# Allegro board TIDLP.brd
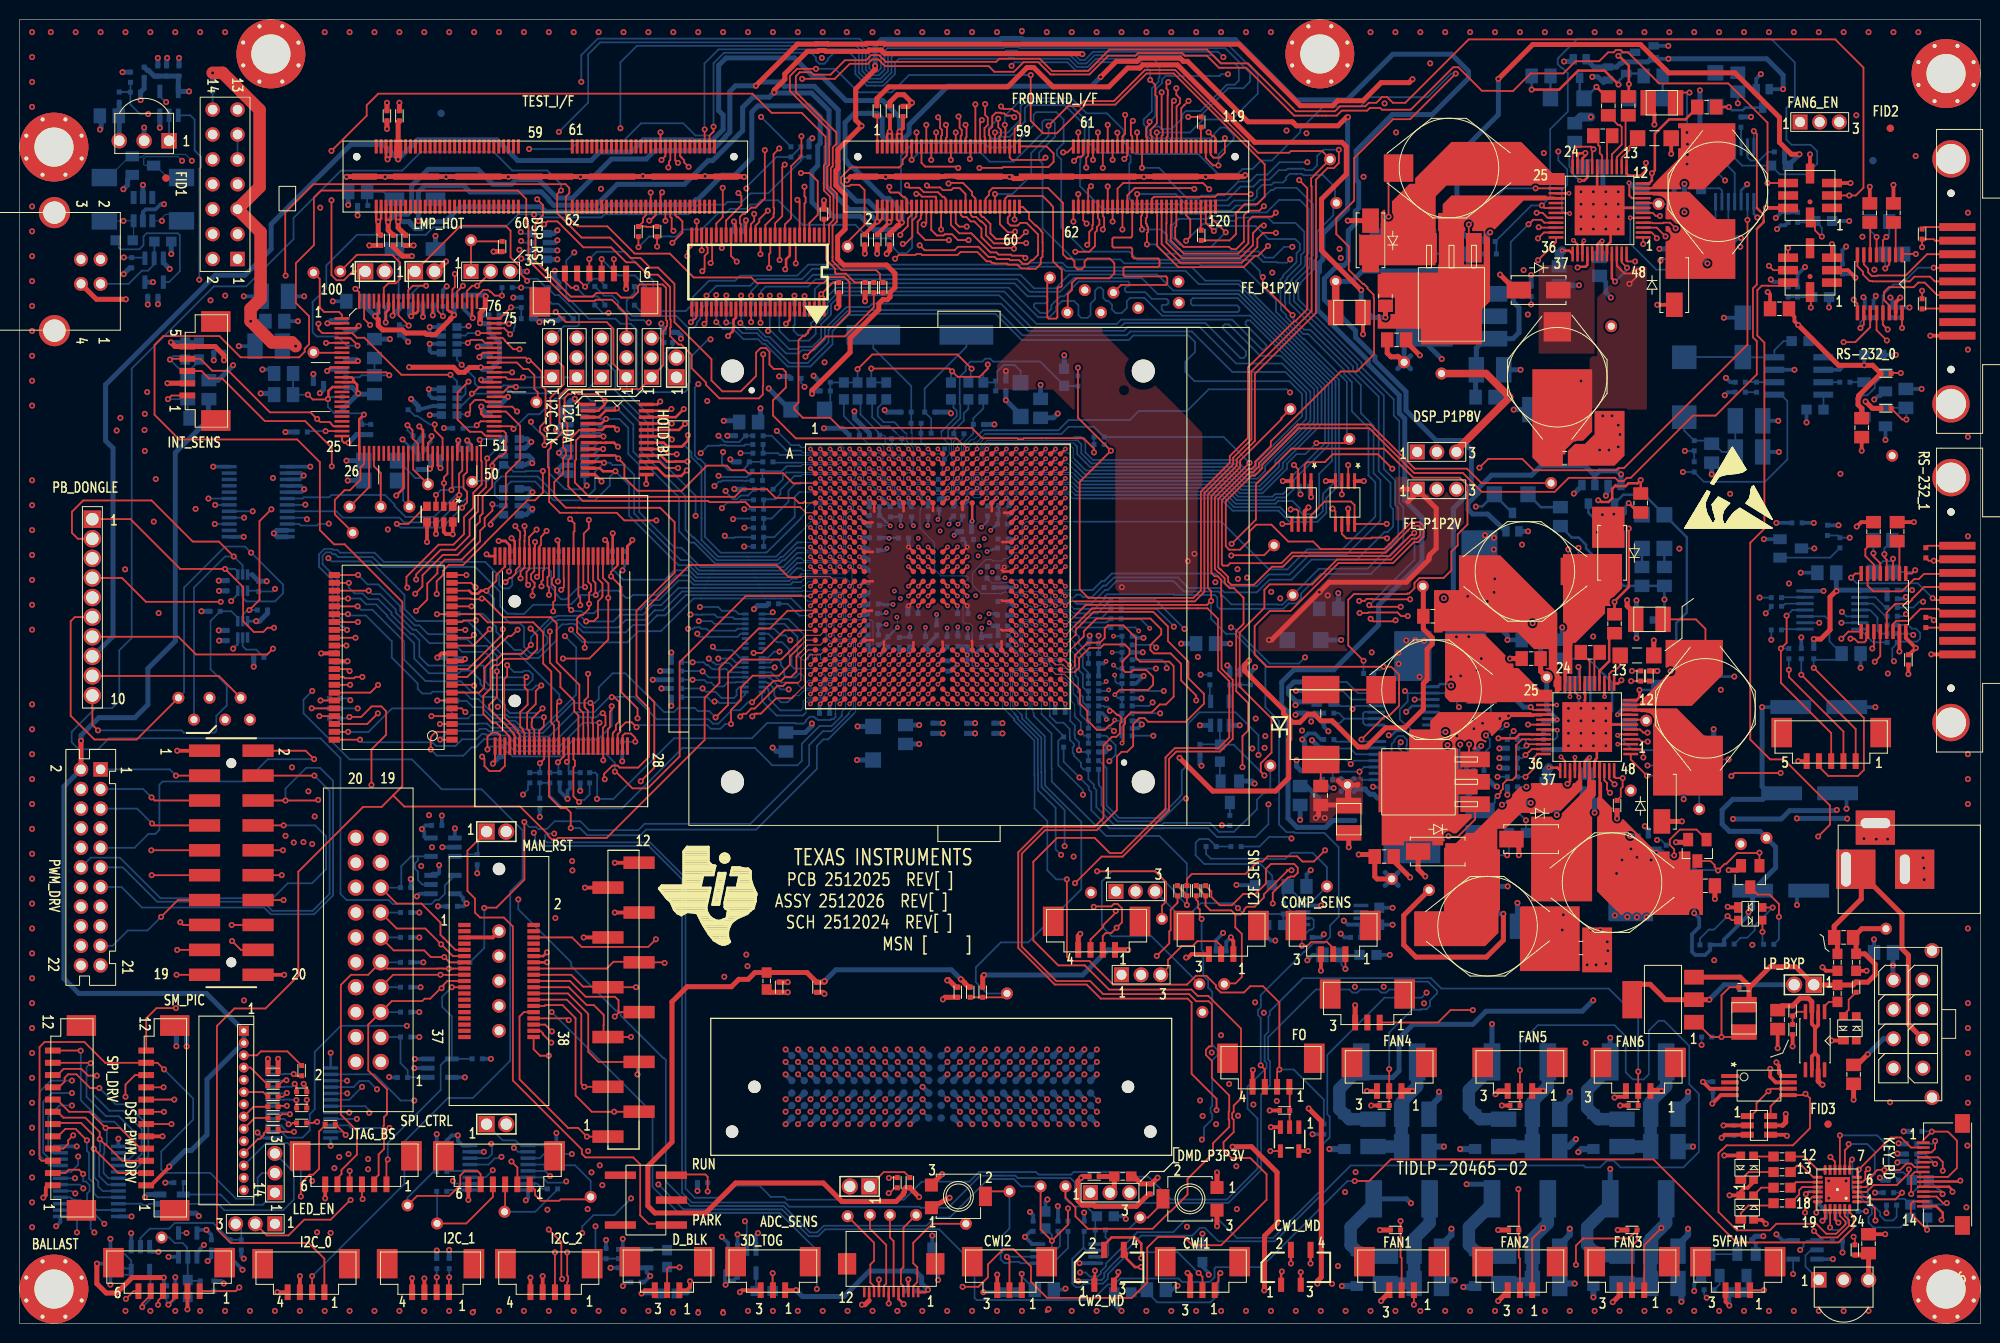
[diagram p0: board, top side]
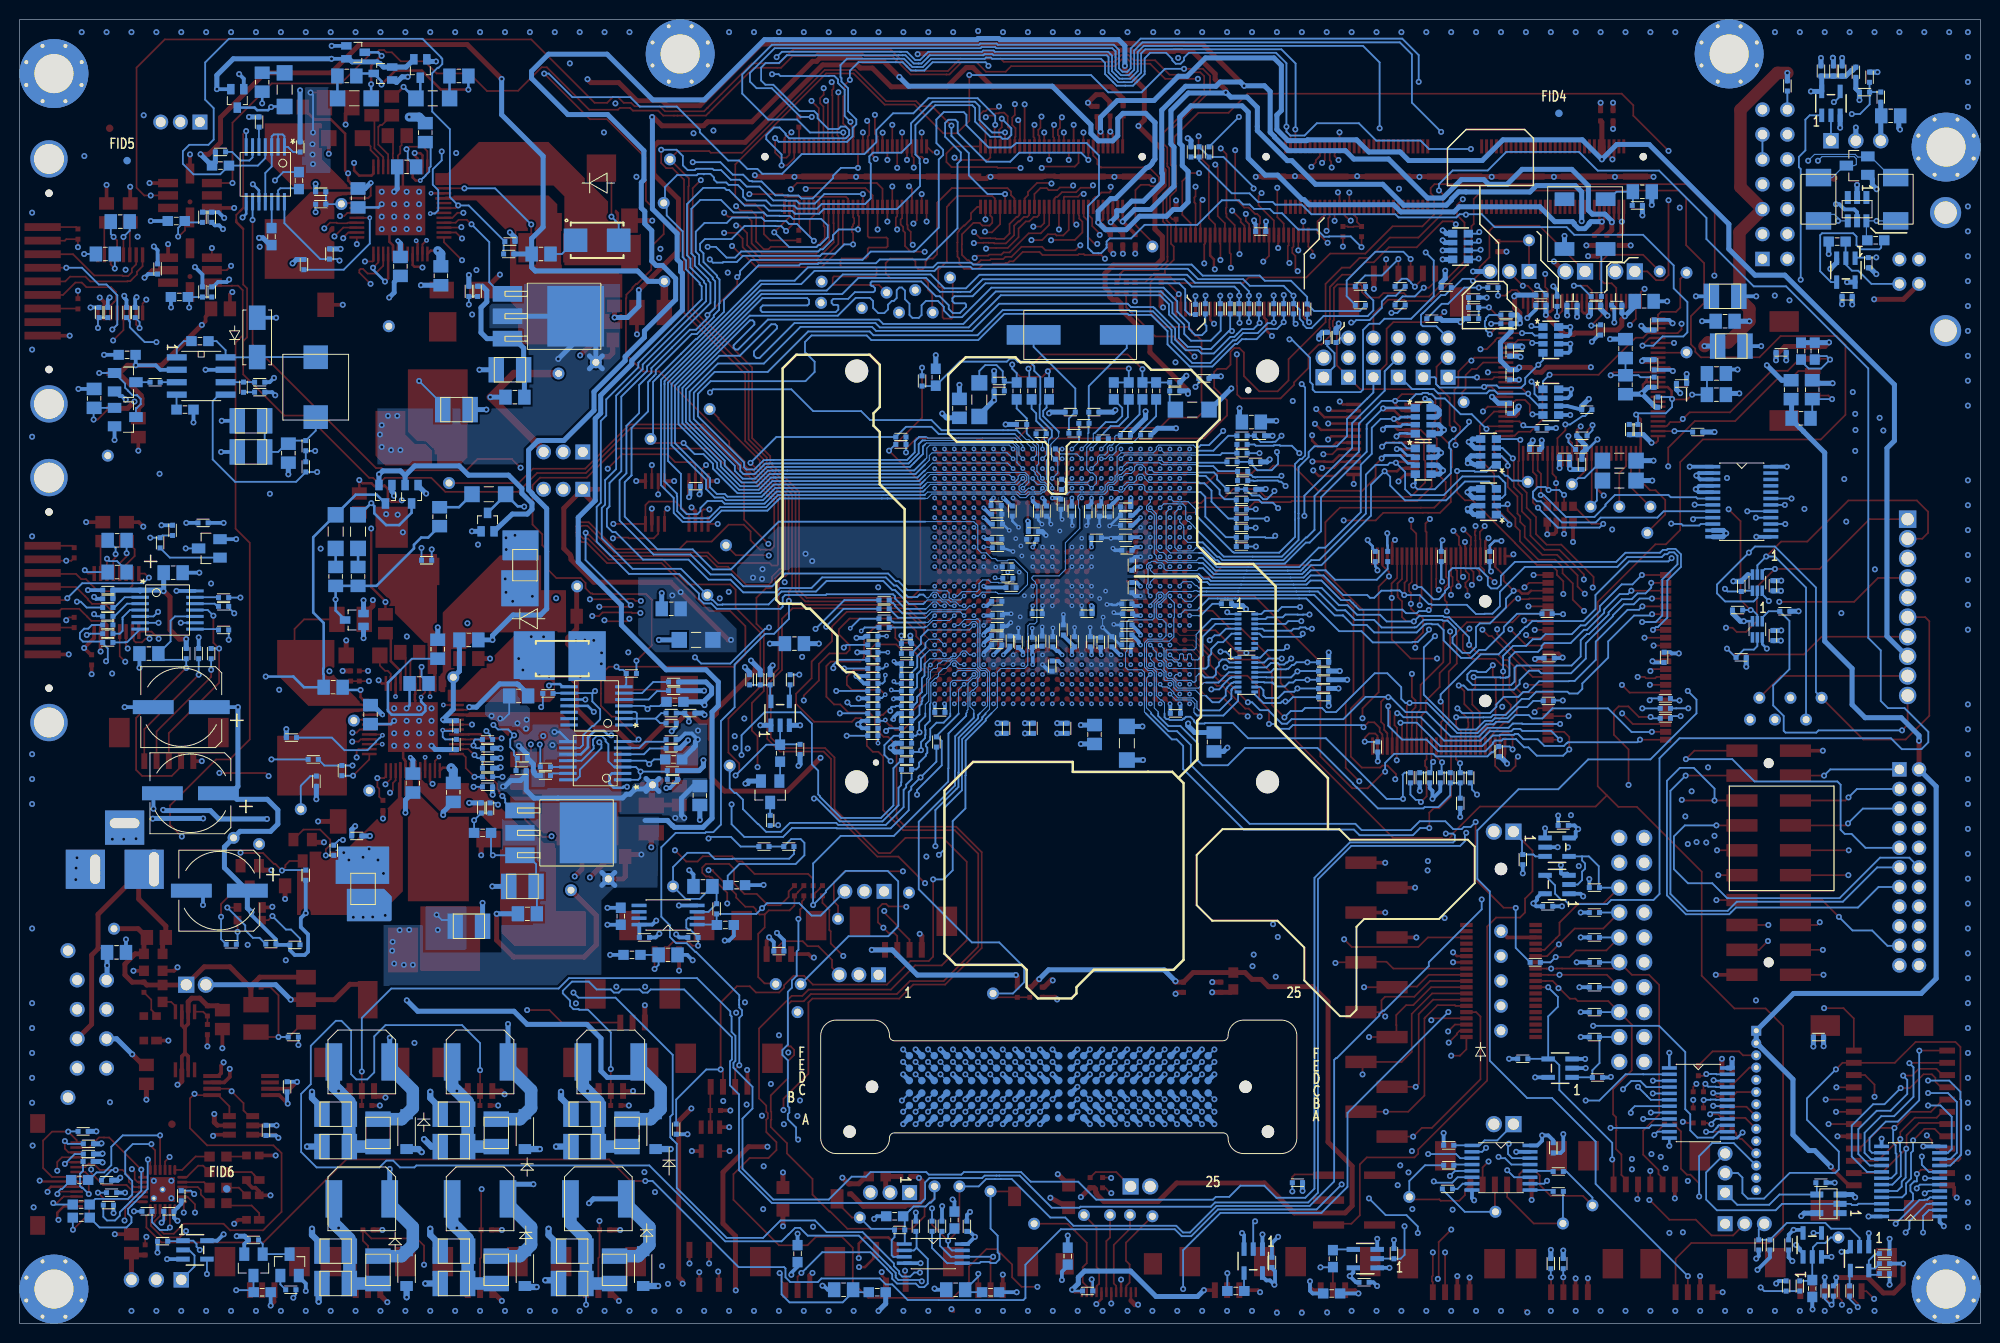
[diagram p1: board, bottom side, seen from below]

Outline 200 x 132.99 mm; copper layers: TOP, LY2GND, LY3, LY4, LY5PWR, BOTTOM. Coordinates in mm from the lower left corner of the outline.
Outline path: 0,132.99 0,0 200,0 200,132.99 0,132.99

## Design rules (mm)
net group DDA00: nets DDA00_N DDA00_P
net group 10: nets CWCTR2 CWY1A CWY1B CWY1C CWY2A CWY2B CWY2C OUT1A_SNUB OUT1B OUT1B_SNUB OUT1C OUT1C_SNUB OUT2A OUT2A_SNUB OUT2B OUT2B_SNUB OUT2C OUT2C_SNUB
net group 20: nets FAN1_SW FAN2_SW FAN4_SW FAN5_SW FAN6_SW FAN6_SW_JUMP
net group 30: nets BT656_A_CLK P_CLK1 P_CLK2 P_CLK3 XTAL_IN XTAL_OUT
net group BT656: nets BT656_CLK BT656_D0 BT656_D1 BT656_D2 BT656_D3 BT656_D4 BT656_D5 BT656_D6 BT656_D7 BT656_D8 BT656_D9
net group BT656_A: nets BT656_A_D0 BT656_A_D1 BT656_A_D2 BT656_A_D3 BT656_A_D4 BT656_A_D5 BT656_A_D6 BT656_A_D7 BT656_A_D8 BT656_A_D9
net group BT656_B: nets BT656_B_CLK BT656_B_D0 BT656_B_D1 BT656_B_D2 BT656_B_D3 BT656_B_D4 BT656_B_D5 BT656_B_D6 BT656_B_D7 BT656_B_D8 BT656_B_D9
net group CLK: nets A_SSP0_CLK ADC_SCLK NC0119 NC0120 OCLKA_RES SP_WAVE_CLK SSP0_CLK_DMD SSP1_CLK SSP2_CLK TRACECLK XCLKIN XCLKOUT
net group DDA: nets DCLKA_N DCLKA_P DDA01_N DDA01_P DDA02_N DDA02_P DDA03_N DDA03_P DDA04_N DDA04_P DDA05_N DDA05_P DDA06_N DDA06_P DDA07_N DDA07_P DDA08_N DDA08_P DDA09_N DDA09_P DDA10_N DDA10_P DDA11_N DDA11_P DDA12_N DDA12_P DDA13_N DDA13_P DDA14_N DDA14_P DDA15_N DDA15_P SCTRLA_N SCTRLA_P
net group DDB: nets DCLKB_N DCLKB_P DDB00_N DDB00_P DDB01_N DDB01_P DDB02_N DDB02_P DDB03_N DDB03_P DDB04_N DDB04_P DDB05_N DDB05_P DDB06_N DDB06_P DDB07_N DDB07_P DDB08_N DDB08_P DDB09_N DDB09_P DDB10_N DDB10_P DDB11_N DDB11_P DDB12_N DDB12_P DDB13_N DDB13_P DDB14_N DDB14_P DDB15_N DDB15_P SCTRLB_N SCTRLB_P
net group DIFF_SP: nets USB_DAT_N USB_DAT_NS USB_DAT_P USB_DAT_PS
net group GPIO: nets GPIO_40 GPIO_41 GPIO_42 GPIO_43 GPIO_44 GPIO_45 GPIO_46 GPIO_47 GPIO_48 GPIO_49 GPIO_50
net group P1_CLK BUS: nets AFE_CLK EXT_CLK P1_A0 P1_A1 P1_A2 P1_A3 P1_A4 P1_A5 P1_A6 P1_A7 P1_A8 P1_A9 P1_B0 P1_B1 P1_B2 P1_B3 P1_B4 P1_B5 P1_B6 P1_B7 P1_B8 P1_B9 P1_C0 P1_C1 P1_C2 P1_C3 P1_C4 P1_C5 P1_C6 P1_C7 P1_C8 P1_C9 P1_HSYNC P1_VSYNC P2_A0 P2_A1 P2_A2 P2_A3 P2_A4 P2_A5 P2_A6 P2_A7 P2_A8 P2_A9 P2_B0 P2_B1 P2_B2 P2_B3 P2_B4 P2_B5 P2_B6 P2_B7 P2_B8 P2_B9 P2_C0 P2_C1 P2_C2 P2_C3 P2_C4 P2_C5 P2_C6 P2_C7 P2_C8 P2_C9 P2_HSYNC P_DATAEN1 P_DATAEN2
net group PM_: nets PM_ADR_21 PM_ADR_22 PM_BLS0 PM_BLS0S PM_BLS1 PM_BLS1S PM_DAT_0 PM_DAT_1 PM_DAT_2 PM_DAT_3 PM_DAT_4 PM_DAT_5 PM_DAT_6 PM_DAT_7 PM_DAT_8 PM_DAT_9 PM_DAT_10 PM_DAT_11 PM_DAT_12 PM_DAT_13 PM_DAT_14 PM_DAT_15 PM_OESZ PM_OEZ PM_SRAM_CSSZ PM_SRAM_CSZ PM_WESZ PM_WEZ
net group PWR: nets A1P8V DMD_P3P3V DMDSPARE0 FE_P1P2V LP_P3P3V MC_VCC P2P5V_CONN P3P3V_CONN P3P3V_EX P3P3V_LP P5V P5V_CONN P5V_IR P5V_IR_CONN P12V_FIL P12V_IN SWNODE2_CORE
net group TRACEPKT_BGA: nets PIPESTAT0R PIPESTAT1R PIPESTAT2R TRACECLKR TRACEPKT0R TRACEPKT1R TRACEPKT2R TRACEPKT3R TRACEPKT4R TRACEPKT5R TRACEPKT6R TRACEPKT7R TRACESYNCR
net group TRACEPT_BUS: nets PIPESTAT0 PIPESTAT1 PIPESTAT2 TRACEPKT0 TRACEPKT1 TRACEPKT2 TRACEPKT3 TRACEPKT4 TRACEPKT5 TRACEPKT6 TRACEPKT7 TRACESYNC
net group U53: nets A1P8V_SENSE CWCTR1 FAN3_SW MTR_ARSTZ N16827292 N16830205 N16830576 N16830606 OCLKA OUT1A P_INTZ PGOOD PMD1K_CP1 PMD1K_FB_LIN1 PMD1K_FB_MOT1 PMD1K_FB_P3P3V PMD1K_FB_P5V PMD1K_GD_CORE PMD1K_GM_IN1 PMD1K_SENSE_MOT1 PMD1K_VCP PMD1K_VREG PMD_INTZ POSENSE PSENS PWRGOOD SSP0_CLK SWNODE_CORE SWNODE_MOT SWNODE_P3P3V SWNODE_P5V

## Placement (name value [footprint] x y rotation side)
ASY1  -  []  20.32 49.53 180 bottom
C1  22 uF  [CAP_1210]  167.51 124.52 0 top
C2  -  [CAP_0402]  37.47 123.19 90 top
C3  -  [CAP_0402]  38.73 123.19 90 top
C4  -  [CAP_0402]  88.77 123.7 90 top
C5  -  [CAP_0402]  90.11 123.63 90 top
C6  -  [CAP_0805]  161.48 121.16 0 top
C7  -  [CAP_0805]  188.72 113.28 90 top
C8  -  [CAP_0805]  191.13 113.28 90 top
C9  -  [CAP_0402]  36.83 110.49 270 top
C10  -  [CAP_0402]  38.1 110.49 270 top
C11  -  [CAP_0402]  39.37 110.49 270 top
C12  -  [CAP_0402]  86.21 110.54 270 top
C13  -  [CAP_0402]  87.48 110.54 270 top
C14  -  [CAP_0402]  88.75 110.54 270 top
C15  -  [CAP_1206]  80.39 93.22 180 bottom
C16  -  [CAP_1206]  102.11 94.23 270 bottom
C17  47 uF  [CAP_1210]  135.64 103.12 180 top
C18  -  [CAP_0805]  179.51 103.5 180 top
C19  -  [CAP_0805]  187.9 91.38 270 top
C20  -  [CAP_0805]  189.1 80.77 90 top
C21  -  [CAP_0805]  191.52 80.77 90 top
C22  22 uF  [CAP_1210]  166.24 71.82 0 top
C23  -  [CAP_0805]  154.18 67.82 0 top
C24  -  [CAP_0805]  160.21 68.45 0 top
C25  -  [CAP_0402]  166.24 66.04 270 top
C26  -  [CAP_0402]  192.66 67.69 90 top
C27  47 uF  [CAP_1210]  135.57 51.44 90 top
C28  -  [CAP_0603]  185.42 36.83 90 top
C29  -  [CAP_0603]  187.32 36.83 90 top
C30  -  [CAP_0402]  77.47 34.29 270 top
C31  -  [CAP_0402]  81.28 34.29 90 top
C32  10 uF  [CAP_1210]  175.9 31.11 270 top
C33  -  [CAP_0805]  179.32 30.99 90 top
C34  -  [CAP_0402]  25.84 25.65 180 top
C35  -  [CAP_0402]  109.6 14.99 0 top
C36  -  [CAP_0402]  115.32 13.72 90 top
C37  -  [CAP_0805]  188.59 8.13 270 top
C500  -  [CAP_0805]  175.26 126.62 90 bottom
C501  -  [CAP_0805]  166.62 127.25 0 bottom
C502  -  [CAP_0805]  155.19 127.25 0 bottom
C503  -  [CAP_0402]  16.26 127.76 270 bottom
C504  -  [CAP_0402]  14.1 127.76 270 bottom
C505  -  [CAP_0805]  158.62 121.48 90 bottom
C506  -  [CAP_0805]  9.14 123.19 0 bottom
C507  -  [CAP_0805]  189.74 112.39 0 bottom
C508  -  [CAP_0402]  181.36 112.84 270 bottom
C509  -  [CAP_0402]  180.4 112.84 270 bottom
C510  -  [CAP_0603]  179.51 118.11 0 bottom
C511  -  [CAP_0402]  169.29 115.44 180 bottom
C512  -  [CAP_0805]  165.48 114.81 90 bottom
C513  -  [CAP_0805]  160.53 117.98 0 bottom
C514  -  [CAP_0402]  34.99 114.05 180 bottom
C515  -  [CAP_0805]  191.26 109.09 0 bottom
C516  -  [CAP_0402]  185.93 107.57 90 bottom
C517  -  [CAP_0402]  181.36 105.22 270 bottom
C518  -  [CAP_0402]  180.4 105.22 270 bottom
C519  -  [CAP_0805]  161.16 107.82 90 bottom
C520  -  [CAP_0805]  157.04 106.87 90 bottom
C521  -  [CAP_0402]  100.08 95.12 0 bottom
C522  -  [CAP_0402]  82.17 96.01 180 bottom
C523  -  [CAP_0402]  73.41 111.38 0 bottom
C524  -  [CAP_0402]  51.69 104.65 180 bottom
C525  22 uF  [CAP_1210]  26.04 104.78 0 bottom
C526  -  [CAP_0402]  13.59 104.78 180 bottom
C527  -  [CAP_0603]  189.04 98.81 180 bottom
C528  -  [CAP_0603]  181.61 100.2 180 bottom
C529  47 uF  [CAP_1210]  149.99 97.28 180 bottom
C530  -  [CAP_0402]  48.01 99.19 90 bottom
C531  -  [CAP_0402]  44.83 103.89 0 bottom
C532  -  [CAP_0402]  41.66 103.89 180 bottom
C533  -  [CAP_0402]  39.24 103.89 0 bottom
C534  -  [CAP_0402]  37.08 103.89 0 bottom
C535  -  [CAP_0805]  34.29 104.27 180 bottom
C536  -  [CAP_0402]  33.27 101.85 90 bottom
C537  -  [CAP_0402]  33.27 97.79 270 bottom
C538  22 uF  [CAP_1210]  25.4 99.69 180 bottom
C539  -  [CAP_0603]  16.89 99.19 90 bottom
C540  -  [CAP_0805]  192.41 94.36 90 bottom
C541  -  [CAP_0603]  183.13 93.22 0 bottom
C542  -  [CAP_0402]  177.16 95.5 270 bottom
C543  47 uF  [CAP_1210]  176.4 92.08 0 bottom
C544  -  [CAP_0402]  175.51 96.01 180 bottom
C545  47 uF  [CAP_1210]  155.45 93.22 0 bottom
C546  -  [CAP_0402]  93.71 85.59 90 bottom
C547  -  [CAP_0402]  89.47 90.25 180 bottom
C548  -  [CAP_0402]  87.21 90.6 180 bottom
C549  -  [CAP_0402]  95.8 90.75 0 bottom
C550  -  [CAP_0402]  85.14 90.62 180 bottom
C551  -  [CAP_0603]  106.55 96.52 270 bottom
C552  -  [CAP_0805]  104.14 93.34 90 bottom
C553  -  [RES_0402]  90.42 92.96 180 bottom
C554  -  [RES_0402]  92.84 92.96 0 bottom
C555  -  [CAP_0805]  74.36 91.95 180 bottom
C556  -  [CAP_0402]  48.01 96.77 270 bottom
C557  -  [CAP_0402]  48.01 93.34 270 bottom
C558  -  [CAP_0805]  36.2 95.76 270 bottom
C559  -  [CAP_0402]  35.81 91.19 270 bottom
C560  -  [CAP_0402]  34.92 91.19 270 bottom
C561  -  [CAP_0402]  33.27 96.01 270 bottom
C562  -  [CAP_0402]  32.89 93.98 270 bottom
C563  -  [CAP_0805]  26.92 94.74 180 bottom
C564  -  [CAP_0805]  19.3 95.25 90 bottom
C565  -  [CAP_0805]  17.14 95.25 90 bottom
C566  47 uF  [CAP_1210]  176.4 88.9 0 bottom
C567  -  [CAP_0402]  131.06 85.41 0 bottom
C568  -  [CAP_0402]  100.39 83.44 180 bottom
C569  -  [CAP_0402]  93.79 83.57 270 bottom
C570  -  [CAP_0402]  87.19 83.31 0 bottom
C571  -  [CAP_0402]  45.47 89.15 0 bottom
C572  -  [CAP_0402]  42.42 88.39 180 bottom
C573  -  [CAP_0402]  40.77 89.15 180 bottom
C574  -  [CAP_1206]  36.83 88.01 180 bottom
C575  -  [CAP_1206]  36.83 85.98 180 bottom
C576  -  [CAP_0805]  190.06 79.88 0 bottom
C577  -  [CAP_0805]  190.06 76.64 0 bottom
C578  -  [CAP_0805]  184.34 76.58 180 bottom
C579  -  [CAP_0402]  181.29 81.66 180 bottom
C580  -  [CAP_0805]  167.77 76.2 90 bottom
C581  -  [CAP_0805]  165.48 76.2 90 bottom
C582  -  [CAP_0805]  157.16 82.29 90 bottom
C583  22 uF  [CAP_1210]  148.46 77.34 270 bottom
C584  -  [CAP_0402]  97.8 91.7 0 bottom
C585  -  [CAP_0402]  99.25 77.19 180 bottom
C586  -  [CAP_0402]  100.33 82.55 180 bottom
C587  -  [CAP_0402]  100.33 80.01 180 bottom
C588  -  [CAP_0402]  100.27 79.12 180 bottom
C589  -  [CAP_0402]  98.87 75.06 180 bottom
C590  -  [CAP_0402]  100.27 81.53 180 bottom
C591  -  [CAP_0402]  98.74 82.87 270 bottom
C592  -  [CAP_0402]  96.76 79.98 0 bottom
C593  -  [CAP_0402]  96.58 80.77 180 bottom
C594  -  [CAP_0402]  96.2 82.87 270 bottom
C595  -  [CAP_0402]  95.25 82.87 270 bottom
C596  -  [CAP_0402]  92.67 82.85 270 bottom
C597  -  [CAP_0402]  91 82.8 270 bottom
C598  -  [CAP_0402]  90.17 80.14 180 bottom
C599  -  [CAP_0402]  89.85 82.87 270 bottom
C600  -  [CAP_0402]  88.84 82.8 270 bottom
C601  -  [CAP_0402]  87.19 82.42 0 bottom
C602  -  [CAP_0402]  87.19 81.41 0 bottom
C603  -  [CAP_0402]  87.19 80.14 0 bottom
C604  -  [CAP_0402]  87.06 78.87 0 bottom
C605  -  [CAP_0402]  86.55 77.34 90 bottom
C606  -  [CAP_0402]  54.99 78.23 90 bottom
C607  -  [CAP_0402]  191.01 74.8 180 bottom
C608  -  [CAP_0805]  133.54 72.9 0 bottom
C609  -  [CAP_1206]  131 69.72 0 bottom
C610  -  [CAP_0805]  120.97 69.34 0 bottom
C611  -  [CAP_0402]  112.97 70.1 0 bottom
C612  -  [CAP_0402]  100.33 73.66 180 bottom
C613  -  [CAP_0402]  100.33 70.17 180 bottom
C614  -  [CAP_0402]  100.33 69.22 0 bottom
C615  -  [CAP_0402]  100.27 72.26 180 bottom
C616  -  [CAP_0402]  100.27 71.12 180 bottom
C617  -  [CAP_0402]  99 69.6 90 bottom
C618  -  [CAP_0402]  98.11 69.47 90 bottom
C619  -  [CAP_0402]  96.71 69.47 90 bottom
C620  -  [CAP_0402]  96.2 72.39 180 bottom
C621  -  [CAP_0402]  95.69 69.6 90 bottom
C622  -  [CAP_0402]  94.61 69.53 90 bottom
C623  -  [CAP_0402]  93.54 70.74 90 bottom
C624  -  [CAP_0402]  92.39 69.53 90 bottom
C625  -  [CAP_0402]  91.12 72.39 0 bottom
C626  -  [CAP_0402]  90.81 69.53 90 bottom
C627  -  [CAP_0402]  89.73 69.47 90 bottom
C628  -  [CAP_0402]  88.58 69.53 90 bottom
C629  -  [CAP_0402]  87.06 73.41 0 bottom
C630  -  [CAP_0402]  87.06 71.25 0 bottom
C631  -  [CAP_0402]  87.06 70.23 0 bottom
C632  -  [CAP_0402]  87.06 69.22 0 bottom
C633  -  [CAP_0402]  87 72.39 0 bottom
C634  -  [CAP_0402]  86.55 75.06 270 bottom
C635  -  [CAP_0402]  21.16 75.25 270 bottom
C636  -  [CAP_0402]  21.16 70.17 270 bottom
C637  -  [CAP_0805]  186.82 68.33 180 bottom
C638  -  [CAP-FK-V-CASEE_PAN]  183.51 62.87 90 bottom
C639  -  [CAP_0805]  164.21 62.1 90 bottom
C640  -  [CAP_0805]  159.26 65.28 0 bottom
C641  -  [CAP_0805]  157.35 68.77 90 bottom
C642  -  [CAP_0603]  133.16 63.4 180 bottom
C643  -  [CAP_0402]  131.64 62.26 0 bottom
C644  -  [CAP_0402]  125.54 65.66 270 bottom
C645  -  [CAP_0402]  94.35 88.68 90 bottom
C646  -  [CAP_0402]  112.97 68.45 0 bottom
C647  -  [CAP_0402]  112.97 66.04 0 bottom
C648  -  [CAP_0402]  112.97 65.28 0 bottom
C649  -  [CAP_0402]  112.97 63.75 0 bottom
C650  -  [CAP_0402]  112.97 61.47 0 bottom
C651  -  [CAP_0402]  112.97 60.71 0 bottom
C652  -  [CAP_0402]  109.54 66.04 0 bottom
C653  -  [CAP_0402]  109.54 63.75 0 bottom
C654  -  [CAP_0402]  109.54 62.23 0 bottom
C655  -  [CAP_0402]  109.54 61.47 0 bottom
C656  -  [CAP_0402]  106.13 62.33 0 bottom
C657  -  [CAP_0402]  99.38 60.71 270 bottom
C658  -  [CAP_0402]  96.58 60.71 270 bottom
C659  -  [CAP_0402]  94.68 67.06 270 bottom
C660  -  [CAP_0402]  93.15 60.71 270 bottom
C661  -  [CAP_0402]  82.11 62.23 180 bottom
C662  -  [CAP_0402]  32.26 67.94 90 bottom
C663  -  [CAP_0402]  43.98 67.87 0 bottom
C664  -  [CAP-FK-V-CASEE_PAN]  182.58 54.08 90 bottom
C665  -  [CAP_0805]  159.89 55.12 90 bottom
C666  -  [CAP_0805]  155.77 54.17 90 bottom
C667  -  [CAP_0603]  133.29 57.53 180 bottom
C668  -  [CAP_0805]  130.62 53.85 270 bottom
C669  -  [CAP_0805]  90.36 60.07 270 bottom
C670  -  [CAP_1206]  87.06 59.18 270 bottom
C671  -  [CAP_0805]  78.17 59.31 270 bottom
C672  -  [CAP-FK-V-CASEE_PAN]  179.63 44.14 90 bottom
C673  -  [CAP_0402]  165.61 49.72 0 bottom
C674  22 uF  [CAP_1210]  164.97 44.32 90 bottom
C675  -  [CAP_0603]  152.78 50.04 180 bottom
C676  47 uF  [CAP_1210]  148.72 44.58 180 bottom
C677  -  [CAP_0805]  130.3 44.58 180 bottom
C678  -  [CAP_0603]  126.87 44.7 0 bottom
C679  -  [CAP_0402]  42.55 50.8 180 bottom
C680  47 uF  [CAP_1210]  154.18 40.51 0 bottom
C681  -  [CAP_0603]  138.68 41.53 270 bottom
C682  -  [CAP_0603]  137.54 37.59 180 bottom
C683  -  [CAP_0402]  136.27 39.37 0 bottom
C684  -  [CAP_0402]  122.56 37.97 0 bottom
C685  -  [CAP_0402]  44.13 42.55 0 bottom
C686  -  [CAP_0402]  16.51 29.21 180 bottom
C687  -  [CAP_0402]  172.72 24.13 90 bottom
C688  -  [CAP_0402]  174.88 19.68 270 bottom
C689  22 uF  [CAP_1210]  167.77 18.03 180 bottom
C690  22 uF  [CAP_1210]  155.7 18.03 180 bottom
C691  22 uF  [CAP_1210]  142.37 18.03 180 bottom
C692  -  [CAP_0402]  43.56 17.91 90 bottom
C693  -  [CAP_0402]  184.78 11.43 0 bottom
C694  -  [CAP_0603]  120.65 7.11 90 bottom
C695  -  [CAP_0402]  103.38 9.91 270 bottom
C696  -  [CAP_0603]  93.09 6.86 270 bottom
C697  -  [CAP_0402]  72.26 6.22 270 bottom
C698  -  [CAP_0402]  19.56 8 90 bottom
C699  -  [CAP_0603]  175.26 3.17 0 bottom
C700  22 uF  [CAP_1210]  167.77 4.06 180 bottom
C701  22 uF  [CAP_1210]  155.7 4.06 180 bottom
C702  22 uF  [CAP_1210]  143.64 4.06 180 bottom
C703  -  [CAP_0603]  112.52 3.17 0 bottom
C704  -  [CAP_0603]  100.97 3.17 0 bottom
C705  -  [CAP_0402]  91.06 3.3 0 bottom
C706  -  [CAP_0603]  66.17 3.05 0 bottom
C707  -  [CAP_0402]  62.87 4.19 0 bottom
C708  -  [CAP_0603]  17.14 3.56 90 bottom
C709  -  [CAP_0402]  9.78 5.08 0 bottom
D1  -  [DIO-SMA]  137.79 110.49 90 top
D2  -  [DIO-SMA]  154.94 105.41 180 top
D3  -  [DIO-SMA]  168.78 105.92 270 top
D4  -  [DIO-SMA]  162.43 78.61 90 top
D5  -  [SMC_ST]  132.72 61.09 90 top
D6  -  [DIO-SMA]  167.51 53.21 270 top
D7  -  [DIO-SMA]  144.65 48.13 180 top
D8  -  [DIO-SMA]  154.18 49.4 180 top
D9  -  [LED_S_TYPE]  176.53 41.78 0 top
D10  -  [LED_S_TYPE]  186.69 30.1 90 top
D11  -  [LED_S_TYPE]  176.21 15.88 90 top
D12  -  [LED_S_TYPE]  176.21 11.81 90 top
D500  -  [DIO-SMB]  141.1 110.49 180 bottom
D501  -  [DIO_SMA]  175.77 100.58 270 bottom
D502  -  [DIO-SMB]  144.65 67.82 180 bottom
D503  -  [SOD-123]  160.53 19.56 270 bottom
D504  -  [SOD-123]  148.46 19.56 270 bottom
D505  -  [SOD-123]  135.13 19.56 270 bottom
D506  -  [SOD-123]  160.53 5.59 270 bottom
D507  -  [SOD-123]  148.46 5.59 270 bottom
D508  -  [SOD-123]  136.4 5.59 270 bottom
DN500  -  [SOT_323]  177.8 124.97 180 bottom
DN501  -  [SOT_323]  165.74 129.67 90 bottom
DN502  -  [SOT_323]  162.94 127.51 270 bottom
DN503  -  [SOT_323]  159.13 128.02 180 bottom
DN504  -  [SOT23AVXC]  12.57 118.11 270 bottom
DN505  -  [SOT_323]  162.69 84.58 180 bottom
DN506  -  [SOT_323]  160.02 84.58 180 bottom
DN507  -  [SOT_323]  152.27 81.74 0 bottom
DN508  -  [SOT_323]  165.86 71.75 270 bottom
FB1  -  [FLTR_0603]  84.07 95.12 270 bottom
FB2  -  [FLTR_0603]  85.47 95.12 270 bottom
FB3  -  [FLTR_0603]  96.77 95.12 270 bottom
FB4  -  [FLTR_0603]  86.87 95.12 270 bottom
FB5  -  [FLTR_0603]  88.39 95.12 270 bottom
FB6  -  [FLTR_0603]  95 95.12 270 bottom
FB7  -  [FLTR_0603]  98.3 95.12 270 bottom
FB8  -  [IND_0805]  186.06 39.37 0 top
FB9  -  [FLTR_0603]  76.2 34.92 270 top
FB10  -  [FLTR_0603]  112.52 14.99 0 top
FB500  -  [0805AVX]  34.48 115.44 180 bottom
FB501  -  [0805AVX]  36.2 99.44 90 bottom
FB502  -  [0805AVX]  26.04 102.23 0 bottom
FB503  -  [0805AVX]  26.92 96.9 180 bottom
FB504  -  [0805AVX]  18.29 92.33 0 bottom
J1  -  [HDR14-87227_AMP]  22.23 108.58 90 top
J2  -  [CN120_QTH_SAMTEC]  53.62 116.99 0 top
J3  -  [CN120_QTH_SAMTEC]  104.74 116.99 0 top
J4  -  [HDR1X3-TMM1030X-X-S_SAM]  181.61 122.56 0 top
J5  -  [CONN4-67068-1000_MOLEX]  8.26 106.05 270 top
J6  -  [HDR2_2MM]  35.24 107.31 0 top
J7  -  [HDR2_2MM]  40.32 107.31 0 top
J8  -  [HDR1X3-TMM1030X-X-S_SAM]  46.04 107.31 0 top
J9  -  [CONN6-53398-0690_MOLEX]  58.74 106.05 0 top
J10  -  [KYCON-CN9SMTA]  197.33 106.3 270 top
J11  -  [CONN5-53398-0590_MOLEX]  18.16 97.16 90 top
J12  -  [HDR1X3-TMM1030X-X-S_SAM]  54.29 96.52 90 top
J13  -  [HDR1X3-TMM1030X-X-S_SAM]  56.83 96.52 90 top
J14  -  [HDR1X3-TMM1030X-X-S_SAM]  59.37 96.52 90 top
J15  -  [HDR1X3-TMM1030X-X-S_SAM]  61.91 96.52 90 top
J16  -  [HDR1X3-TMM1030X-X-S_SAM]  64.45 96.52 90 top
J17  -  [HDR2_2MM]  66.99 96.52 90 top
J18  -  [HDR1X3-TMM1030X-X-S_SAM]  142.56 88.9 0 top
J19  -  [HDR1X3-TMM1030X-X-S_SAM]  142.56 85.09 0 top
J20  -  [CONN10-SQT_SAM]  7.42 82.04 0 top
J21  -  [KYCON-CN9SMTA]  197.33 73.79 270 top
J22  -  [CONN5-53398-0590_MOLEX]  184.78 58.42 180 top
J23  -  [CONN22-B22B-PHD_JST]  8.26 56.52 180 top
J24  -  [CONN20-TSM-110-0X-X-DV-A_SAMTEC]  21.59 46.99 270 top
J25  -  [HDR2_2MM]  47.62 50.16 0 top
J26  -  [HDR1X3-TMM1030X-X-S_SAM]  111.82 44.07 0 top
J27  -  [JACK3-DCPOWER_CUI_MOD]  186.3 46.32 0 top
J28  -  [HDR10X2-5103308_TYCO]  36.83 26.67 180 top
J29  -  [CONN4-53398_MOLEX]  109.86 38.1 180 top
J30  -  [CN3_53398_MOLEX]  122.56 38.73 180 top
J31  -  [CN3_53398_MOLEX]  133.99 38.73 180 top
J32  -  [MICTOR_HPA]  48.9 34.92 90 top
J33  -  [CONN12-SMT-TSM-112-SV_SAMTEC]  61.59 33.02 0 top
J34  -  [HDR1X3-TMM1030X-X-S_SAM]  112.39 35.56 0 top
J35  -  [CN3_53398_MOLEX]  137.48 31.75 180 top
J36  -  [HDR2_2MM]  183.01 34.54 180 top
J37  -  [CONN8-43045-0813_MOLEX]  191.13 26.04 270 top
J38  -  [CONN12-53398_MOLEX]  4.45 20.95 90 top
J39  -  [CONN12-53398_MOLEX]  13.97 20.95 90 top
J40  -  [CONN14-53048_MLX]  22.86 29.84 0 top
J41  -  [CONN4-53398_MOLEX]  127.64 24.13 180 top
J42  -  [CN3_53398_MOLEX]  139.7 24.77 180 top
J43  -  [CN3_53398_MOLEX]  153.03 24.77 180 top
J44  -  [CN3_53398_MOLEX]  165.1 24.77 180 top
J45  -  [HDR1X3-TMM1030X-X-S_SAM]  26.04 10.16 180 top
J46  -  [HDR1X3-TMM1030X-X-S_SAM]  26.04 13.34 90 top
J47  -  [CONN6-53398-0690_MOLEX]  34.29 15.24 180 top
J48  -  [HDR2_2MM]  47.62 20.32 0 top
J49  -  [CONN6-53398-0690_MOLEX]  48.9 15.24 180 top
J50  -  [HDR2_2MM]  86.68 13.97 180 top
J51  -  [HDR1X3-TMM1030X-X-S_SAM]  109.22 13.34 0 top
J52  -  [CONN14-XF2M_OMRON]  194.18 15.19 90 top
J53  -  [CONN6-53398-0690_MOLEX]  15.24 4.34 180 top
J54  -  [CONN4-53398_MOLEX]  29.21 3.17 180 top
J55  -  [CONN4-53398_MOLEX]  41.91 3.17 180 top
J56  -  [CONN4-53398_MOLEX]  53.98 3.17 180 top
J57  -  [CN3_53398_MOLEX]  66.04 4.45 180 top
J58  -  [CN3_53398_MOLEX]  76.83 4.45 180 top
J59  -  [CONN12-FH12_HRS]  88.9 3.17 180 top
J60  -  [CN3_53398_MOLEX]  100.97 4.45 180 top
J61  -  [CONN4-52808_MOLEX]  111.12 5.71 0 top
J62  -  [CN3_53398_MOLEX]  120.65 4.45 180 top
J63  -  [CONN4-52808_MOLEX]  130.18 5.71 0 top
J64  -  [CN3_53398_MOLEX]  140.97 4.45 180 top
J65  -  [CN3_53398_MOLEX]  153.03 4.45 180 top
J66  -  [CN3_53398_MOLEX]  164.47 4.45 180 top
J67  -  [CN3_53398_MOLEX]  175.26 4.45 180 top
J500  -  [CN150CUSTOM_REV]  109.25 20.95 180 bottom
L1  -  [IND_SRR1005]  145.8 117.86 0 top
L2  -  [IND_SRR1005]  173.23 115.44 90 top
L3  -  [IND_SRR1005]  156.84 96.52 90 top
L4  -  [IND_SRR1005]  153.54 76.71 180 top
L5  -  [IND_SRR1005]  144.02 64.64 0 top
L6  -  [IND_SRR1005]  171.96 62.74 90 top
L7  -  [IND_SRR1005]  162.43 44.96 180 top
L8  -  [IND_SRR1005]  149.73 40.51 180 top
L500  -  [IND2-SPR7030_BOU]  169.8 95.5 270 bottom
L501  -  [IND_SERH]  165.1 26.67 180 bottom
L502  -  [IND_SERH]  153.03 26.67 180 bottom
L503  -  [IND_SERH]  139.7 26.67 180 bottom
L504  -  [IND_SERH]  165.1 12.7 180 bottom
L505  -  [IND_SERH]  153.03 12.7 180 bottom
L506  -  [IND_SERH]  140.97 12.7 180 bottom
MT1  -  [MH276-157GND]  25.63 129.5 22.5 top
MT2  -  [MH276-157GND]  132.63 129.5 22.5 top
MT3  -  [MH276-157GND]  196.5 127.5 22.5 top
MT4  -  [MH276-157GND]  3.5 120 22.5 top
MT5  -  [MH276-157GND]  3.5 3.5 292.5 top
MT6  -  [MH276-157GND]  196.5 3.5 22.5 top
NOREF  -  []  0 0 90 top
NOREF#2  -  []  0 -6.35 0 top
NOREF#3  -  [unnamed#2]  184.47 20.32 0 top
NOREF#4  -  []  251.46 79.38 0 top
NOREF#5  -  []  -15.21 -14.47 0 top
NOREF#6  -  []  0 0 90 top
NOREF#7  -  []  174.62 84.71 0 top
NOREF#8  -  []  94.23 119.44 0 top
NOREF#9  -  []  -15.48 146.49 0 top
NOREF#10  -  []  22.23 -57.15 0 top
NOREF#11  -  [unnamed#3]  93.66 76.2 270 top
NOREF#12  -  []  0 -6.35 0 top
NOREF#13  -  [unnamed#2]  14.92 116.84 0 top
NOREF#14  -  [unnamed#2]  190.82 121.92 0 top
NOREF#15  -  []  109.52 19.68 0 top
NOREF#16  -  []  22.28 -57.18 0 top
NOREF#17  -  []  208.31 147.36 0 top
NOREF#18  -  []  148.08 71.88 180 bottom
NOREF#19  -  [unnamed#2]  42.99 123.44 180 bottom
NOREF#20  -  [unnamed#2]  189.04 118.62 180 bottom
NOREF#21  -  [unnamed#2]  178.88 13.72 180 bottom
NOREF#22  -  []  140.97 116.33 180 bottom
Q1  -  [SM_TO_252_DPAK]  146.05 105.41 180 top
Q2  -  [SM_TO_252_DPAK]  144.15 55.24 90 top
Q3  -  [SOT23AVXD]  171.13 48.26 0 top
Q4  -  [SOT23AVXD]  176.53 45.59 0 top
Q5  -  [SOT223]  167.64 33.02 90 top
Q500  -  [SM_TO_252_DPAK]  145.92 102.74 270 bottom
Q501  -  [SOT23AVXD]  189.23 96.01 90 bottom
Q502  -  [SOT23AVXD]  189.23 92.46 90 bottom
Q503  -  [SOT23AVXD]  180.66 79.06 270 bottom
Q504  -  [SOT23AVXD]  123.44 54.23 180 bottom
Q505  -  [SM_TO_252_DPAK]  144.65 50.04 270 bottom
Q506  -  [SOT23-3_FC]  176.15 5.97 180 bottom
Q507  -  [SOT23AVXD]  172.47 5.97 0 bottom
R1  -  [RES_0402]  87.44 123.7 270 top
R2  -  [RES_0402]  120.52 122.56 270 top
R3  -  [RES_0805]  162.05 124.21 90 top
R4  -  [RES_0805]  164.08 124.21 90 top
R5  -  [RES_1206]  166.75 120.9 0 top
R6  -  [RES_0805]  172.09 124.08 0 top
R7  -  [RES_0402]  49.21 109.86 90 top
R8  -  [RES_0402]  63.12 111.38 90 top
R9  -  [RES_0402]  65.02 111.38 90 top
R10  -  [RES_0402]  120.52 111 90 top
R11  -  [RES_0805]  139.32 104.78 270 top
R12  -  [RES_0402]  194.06 111.12 270 top
R13  -  [RES_0402]  194.06 104.01 90 top
R14  -  [RES_0805]  140.46 100.33 0 top
R15  -  [RES_0402]  190.37 96.9 180 top
R16  -  [RES_0402]  190.37 93.34 180 top
R17  -  [RES_0805]  157.61 88.27 0 top
R18  -  [RES_0805]  165.35 83.69 270 top
R19  -  [RES_0805]  144.15 72.14 0 top
R20  -  [RES_0805]  162.69 71.37 90 top
R21  -  [RES_0402]  194.44 78.61 270 top
R22  -  [RES_0402]  194.44 71.5 90 top
R23  -  [RES_1206]  164.97 68.14 0 top
R24  -  [RES_0402]  165.35 66.04 270 top
R25  -  [RES_0805]  132.72 53.85 270 top
R26  -  [RES_0402]  162.94 52.83 90 top
R27  -  [RES_0402]  118.11 44.13 90 top
R28  -  [RES_0402]  119.06 44.13 270 top
R29  -  [RES_0402]  120.02 44.13 90 top
R30  -  [RES_0402]  120.97 44.13 270 top
R31  -  [RES_0805]  139.19 47.62 0 top
R32  -  [RES_0805]  171.96 44.64 0 top
R33  -  [RES_0805]  159.26 38.29 0 top
R34  -  [RES_0402]  95.69 33.78 90 top
R35  -  [RES_0402]  96.96 33.78 270 top
R36  -  [RES_0402]  98.23 33.78 90 top
R37  -  [RES_0402]  175.9 34.29 0 top
R38  -  [RES_0402]  180.85 31.88 270 top
R39  -  [RES_0603]  185.42 33.66 270 top
R40  -  [RES_0402]  187.32 34.29 270 top
R41  -  [RES_0402]  25.84 24.26 180 top
R42  -  [RES_0402]  25.84 23.11 180 top
R43  -  [RES_0402]  25.84 22.1 180 top
R44  -  [RES_0402]  25.84 20.95 180 top
R45  -  [RES_0402]  28.77 25.78 90 top
R46  -  [RES_0402]  28.77 23.62 0 top
R47  -  [RES_0402]  28.77 21.97 0 top
R48  -  [RES_0402]  129.03 21.72 0 top
R49  -  [RES_0402]  139.19 22.23 180 top
R50  -  [RES_0402]  152.53 22.23 180 top
R51  -  [RES_0402]  164.59 22.23 180 top
R52  -  [RES_0402]  180.85 29.97 270 top
R53  -  [RES_0805]  187.07 25.4 90 top
R54  -  [RES_0402]  25.84 19.81 180 top
R55  -  [RES_0402]  28.77 20.45 0 top
R56  -  [RES_0402]  31.69 20.32 180 top
R57  -  [RES_0402]  89.53 14.35 270 top
R58  -  [RES_0402]  90.81 14.35 90 top
R59  -  [RES_0603]  179.77 17.02 180 top
R60  -  [RES_0603]  179.77 15.43 180 top
R61  -  [RES_0603]  179.77 13.84 180 top
R62  -  [RES_0603]  179.77 12.26 180 top
R63  -  [RES_0402]  140.34 9.53 180 top
R64  -  [RES_0402]  152.4 9.53 180 top
R65  -  [RES_0402]  164.47 9.53 180 top
R66  -  [RES_0402]  187.2 7.49 90 top
R500  -  [RES_1206]  172.97 125.86 270 bottom
R501  -  [RES_1206]  165.86 124.97 180 bottom
R502  -  [RES_1206]  157.86 124.97 0 bottom
R503  -  [RES_0402]  19.68 126.24 270 bottom
R504  -  [RES_0402]  14.99 127.76 90 bottom
R505  -  [RES_0402]  12.7 127.64 270 bottom
R506  -  [RES_0402]  11.81 125.6 0 bottom
R507  -  [RES_0402]  11.3 127.13 90 bottom
R508  -  [RES_0402]  10.16 125.09 90 bottom
R509  -  [RES_0402]  179.51 119.51 0 bottom
R510  -  [RES_0402]  175.58 122.56 270 bottom
R511  -  [RES_0402]  171.39 120.02 90 bottom
R512  -  [RES_0603]  184.02 112.46 0 bottom
R513  -  [RES_0603]  171.51 116.59 270 bottom
R514  -  [RES_0402]  169.29 114.17 180 bottom
R515  -  [RES_2010]  16.51 114.68 90 bottom
R516  -  [RES_2010]  8.64 114.68 90 bottom
R517  -  [RES_0603]  183.71 104.71 180 bottom
R518  -  [RES_0603]  174.31 110.87 270 bottom
R519  -  [RES_0402]  171.01 108.01 270 bottom
R520  -  [RES_0402]  168.4 109.09 90 bottom
R521  -  [RES_0402]  154.18 105.28 270 bottom
R522  -  [RES_0402]  153.29 105.28 90 bottom
R523  -  [RES_0402]  150.11 109.09 180 bottom
R524  -  [RES_0402]  149.99 110.36 0 bottom
R525  -  [RES_0805]  146.81 109.09 0 bottom
R526  -  [RES_0402]  100.08 96.14 180 bottom
R527  -  [RES_0402]  82.17 95.12 0 bottom
R528  -  [RES_0402]  78.68 119.51 90 bottom
R529  -  [RES_0402]  88.07 105.66 90 top
R530  -  [RES_0402]  82.04 113.16 270 top
R531  -  [RES_0402]  63.24 105.78 0 bottom
R532  -  [RES_0402]  59.18 105.79 0 bottom
R533  -  [RES_0402]  54.48 105.66 180 bottom
R534  -  [RES_0402]  49.72 105.66 0 bottom
R535  -  [RES_0402]  44.83 104.9 180 bottom
R536  -  [RES_0402]  39.18 104.76 180 bottom
R537  -  [RES_0603]  14.61 110.36 180 bottom
R538  -  [RES_0402]  11.43 108.2 270 bottom
R539  -  [RES_0603]  10.67 110.49 180 bottom
R540  -  [RES_0402]  191.9 103.12 90 bottom
R541  -  [RES_0402]  191.01 103.12 90 bottom
R542  -  [RES_0402]  189.1 103.12 270 bottom
R543  -  [RES_0402]  188.21 103.12 90 bottom
R544  -  [RES_0402]  80.52 119.51 270 bottom
R545  -  [RES_0402]  79.69 119.51 270 bottom
R546  -  [RES_0402]  87.12 105.66 90 top
R547  -  [RES_0402]  86.23 105.66 90 top
R548  -  [RES_0402]  83.57 105.66 90 top
R549  -  [RES_0402]  80.07 103.44 90 bottom
R550  -  [RES_0402]  79.06 103.5 90 bottom
R551  -  [RES_0402]  77.53 103.5 90 bottom
R552  -  [RES_0402]  76.52 103.5 90 bottom
R553  -  [RES_0402]  75.63 103.5 270 bottom
R554  -  [RES_0402]  74.61 103.5 270 bottom
R555  -  [RES_0402]  73.6 103.5 90 bottom
R556  -  [RES_0402]  72.07 103.5 90 bottom
R557  -  [RES_0402]  71.06 103.5 90 bottom
R558  -  [RES_0402]  70.04 103.5 270 bottom
R559  -  [RES_0402]  68.67 103.47 270 bottom
R560  -  [RES_0402]  66.61 100.58 270 bottom
R561  -  [RES_0402]  65.72 100.58 270 bottom
R562  -  [RES_0402]  63.24 103.87 0 bottom
R563  -  [RES_0402]  59.18 103.89 0 bottom
R564  -  [RES_0402]  55.94 102.49 0 bottom
R565  -  [RES_0402]  51.69 103.63 0 bottom
R566  -  [RES_0402]  51.69 102.49 180 bottom
R567  -  [RES_0402]  48.39 102.87 0 bottom
R568  -  [RES_0402]  48.39 101.98 0 bottom
R569  -  [RES_0402]  43.18 104.27 90 bottom
R570  -  [RES_0402]  38.73 101.35 270 bottom
R571  -  [RES_0402]  20.32 99.06 0 bottom
R572  -  [RES_0603]  18.29 99.19 90 bottom
R573  -  [RES_0402]  186.18 96.01 180 bottom
R574  -  [RES_0402]  175.51 95 180 bottom
R575  -  [RES_0402]  170.81 89.53 90 bottom
R576  -  [RES_0805]  149.48 94.49 180 bottom
R577  -  [RES_0402]  110.11 90.42 0 bottom
R578  -  [RES_0402]  110.11 89.66 0 bottom
R579  -  [RES_0402]  107.95 96.14 270 bottom
R580  -  [RES_0402]  91.44 91.82 0 bottom
R581  -  [RES_0402]  92.46 90.81 180 bottom
R582  -  [RES_0402]  44.7 91.31 180 bottom
R583  -  [RES_0402]  40.64 90.55 0 bottom
R584  -  [RES_0402]  40.14 93.21 0 bottom
R585  -  [RES_0402]  30.48 95.89 0 bottom
R586  -  [RES_0402]  28.83 90.93 0 bottom
R587  -  [RES_0805]  172.59 88.77 270 bottom
R588  -  [RES_0402]  170.81 87.38 270 bottom
R589  -  [RES_1206]  152.15 84.58 180 bottom
R590  -  [RES_0402]  75.31 89.66 180 bottom
R591  -  [RES_0402]  75.31 88.77 180 bottom
R592  -  [RES_0402]  75.25 86.93 180 bottom
R593  -  [RES_0402]  75.25 85.98 180 bottom
R594  -  [RES_0402]  75.37 84.01 180 bottom
R595  -  [RES_0402]  75.37 83.06 180 bottom
R596  -  [RES_0402]  75.37 82.11 180 bottom
R597  -  [RES_0402]  79.19 96.4 180 bottom
R598  -  [RES_0402]  40.64 87.63 90 bottom
R599  -  [RES_0402]  185.67 79.63 270 bottom
R600  -  [RES_0402]  184.4 80.9 270 bottom
R601  -  [RES_1206]  167.77 80.77 90 bottom
R602  -  [RES_1206]  165.48 80.77 90 bottom
R603  -  [RES_0402]  158.49 77.85 180 bottom
R604  -  [RES_0402]  99.2 76.02 180 bottom
R605  -  [RES_0402]  75.37 81.15 180 bottom
R606  -  [RES_0402]  75.37 80.2 180 bottom
R607  -  [RES_0402]  75.37 79.25 180 bottom
R608  -  [RES_0402]  61.72 78.23 90 bottom
R609  -  [RES_0402]  60.45 78.23 90 bottom
R610  -  [RES_0402]  50.04 78.23 90 bottom
R611  -  [RES_0402]  191.01 73.91 180 bottom
R612  -  [RES_0402]  191.01 73.03 180 bottom
R613  -  [RES_0402]  191.01 72.14 180 bottom
R614  -  [RES_0402]  191.01 71.25 180 bottom
R615  -  [RES_0402]  191.01 70.36 180 bottom
R616  -  [RES_0402]  191.01 69.47 180 bottom
R617  -  [RES_0402]  179.2 74.04 0 bottom
R618  -  [RES_0402]  179.2 73.15 0 bottom
R619  -  [RES_0402]  179.2 70.74 0 bottom
R620  -  [RES_0805]  154.18 69.72 0 bottom
R621  -  [RES_0402]  112.97 69.22 0 bottom
R622  -  [RES_0402]  111.82 73.79 180 bottom
R623  -  [RES_0402]  111.82 72.9 180 bottom
R624  -  [RES_0402]  111.82 71.88 180 bottom
R625  -  [RES_0402]  111.82 70.99 180 bottom
R626  -  [RES_0402]  109.54 69.34 180 bottom
R627  -  [RES_0402]  76.9 73.41 0 bottom
R628  -  [RES_0402]  44.2 72.39 180 bottom
R629  -  [RES_0402]  183.01 68.33 90 bottom
R630  -  [RES_0402]  181.74 68.33 270 bottom
R631  -  [RES_0402]  180.47 68.33 90 bottom
R632  -  [RES_0805]  168.02 64.9 0 bottom
R633  -  [RES_0402]  155.45 60.96 270 bottom
R634  -  [RES_0805]  149.1 64.01 180 bottom
R635  -  [RES_0402]  146.11 64.26 0 bottom
R636  -  [RES_0402]  137.6 66.29 180 bottom
R637  -  [RES_0402]  133.54 62.26 180 bottom
R638  -  [RES_0402]  133.54 61.24 180 bottom
R639  -  [RES_0402]  133.29 65.43 180 bottom
R640  -  [RES_0402]  133.29 64.54 0 bottom
R641  -  [RES_0402]  124.46 65.66 270 bottom
R642  -  [RES_0402]  123.44 65.66 270 bottom
R643  -  [RES_0402]  121.41 65.66 270 bottom
R644  -  [RES_0402]  112.97 67.69 0 bottom
R645  -  [RES_0402]  112.97 66.8 0 bottom
R646  -  [RES_0402]  112.97 64.52 0 bottom
R647  -  [RES_0402]  112.97 62.99 0 bottom
R648  -  [RES_0402]  112.97 62.23 0 bottom
R649  -  [RES_0402]  109.54 68.33 180 bottom
R650  -  [RES_0402]  109.54 67.31 180 bottom
R651  -  [RES_0402]  109.54 65.28 0 bottom
R652  -  [RES_0402]  109.54 64.52 0 bottom
R653  -  [RES_0402]  109.54 62.99 0 bottom
R654  -  [RES_0402]  109.54 60.71 0 bottom
R655  -  [RES_0402]  66.99 67.44 0 bottom
R656  -  [RES_0402]  66.99 66.55 0 bottom
R657  -  [RES_0402]  66.99 65.66 0 bottom
R658  -  [RES_0402]  66.99 64.77 0 bottom
R659  -  [RES_0402]  66.99 63.88 0 bottom
R660  -  [RES_0402]  44.07 63.5 180 bottom
R661  -  [RES_0402]  32.13 63.75 180 bottom
R662  -  [RES_0402]  32.13 62.74 180 bottom
R663  -  [RES_0402]  32.13 61.72 180 bottom
R664  -  [RES_0402]  24.4 67.94 0 bottom
R665  -  [RES_0402]  172.28 59.75 180 bottom
R666  -  [RES_0402]  170.05 57.53 180 bottom
R667  -  [RES_0402]  169.74 55.31 270 bottom
R668  -  [RES_0402]  167.13 56.39 90 bottom
R669  -  [RES_0402]  155.45 59.05 270 bottom
R670  -  [RES_0402]  152.91 52.58 270 bottom
R671  -  [RES_0402]  152.27 59.56 0 bottom
R672  -  [RES_0402]  152.27 58.67 0 bottom
R673  -  [RES_0402]  152.27 57.66 0 bottom
R674  -  [RES_0402]  152.27 56.64 0 bottom
R675  -  [RES_0402]  152.27 55.75 0 bottom
R676  -  [RES_0402]  152.27 54.74 0 bottom
R677  -  [RES_0402]  152.02 52.58 90 bottom
R678  -  [RES_0402]  148.84 56.39 180 bottom
R679  -  [RES_0402]  148.72 57.66 0 bottom
R680  -  [RES_0402]  146.37 56.77 0 bottom
R681  -  [RES_0402]  146.37 55.88 180 bottom
R682  -  [RES_0402]  133.54 59.56 180 bottom
R683  -  [RES_0402]  133.54 58.67 0 bottom
R684  -  [RES_0402]  133.41 56.39 180 bottom
R685  -  [RES_0402]  133.41 55.5 180 bottom
R686  -  [RES_0402]  123.44 51.31 90 bottom
R687  -  [RES_0603]  122.43 58.17 90 bottom
R688  -  [RES_0402]  120.4 58.55 270 bottom
R689  -  [RES_0402]  112.97 59.94 0 bottom
R690  -  [RES_0402]  109.54 59.94 180 bottom
R691  -  [RES_0402]  109.54 59.18 0 bottom
R692  -  [RES_0402]  109.54 58.29 0 bottom
R693  -  [RES_0402]  109.54 57.4 180 bottom
R694  -  [RES_0402]  109.54 56.52 180 bottom
R695  -  [RES_0402]  106.49 59.31 90 bottom
R696  -  [RES_0402]  61.47 58.8 90 bottom
R697  -  [RES_0402]  58.14 55.66 270 bottom
R698  -  [RES_0402]  57.18 55.66 270 bottom
R699  -  [RES_0402]  56.17 55.66 90 bottom
R700  -  [RES_0402]  55.09 55.66 270 bottom
R701  -  [RES_0402]  54.07 55.66 90 bottom
R702  -  [RES_0402]  53.06 55.66 90 bottom
R703  -  [RES_0402]  53.06 53.06 270 bottom
R704  -  [RES_0402]  52.04 55.66 90 bottom
R705  -  [RES_0402]  49.13 58.33 270 bottom
R706  -  [RES_0402]  170.81 45.72 90 bottom
R707  -  [RES_0402]  167.96 48.26 270 bottom
R708  -  [RES_0402]  124.08 48.64 0 bottom
R709  -  [RES_0402]  121.54 48.64 0 bottom
R710  -  [RES_0402]  69.66 14.35 0 bottom
R711  -  [RES_0402]  46.67 47.31 270 bottom
R712  -  [RES_0402]  39.37 44.45 0 bottom
R713  -  [RES_0805]  190.12 37.85 180 bottom
R714  -  [RES_0402]  174.37 38.69 0 bottom
R715  -  [RES_0402]  178.41 38.67 0 bottom
R716  -  [RES_0402]  171.92 38.61 180 bottom
R717  -  [RES_0805]  148.21 41.78 180 bottom
R718  -  [RES_0805]  133.86 37.59 180 bottom
R719  -  [RES_0402]  131.32 39.37 0 bottom
R720  -  [RES_0402]  128.91 42.29 90 bottom
R721  -  [RES_0603]  128.02 40.64 180 bottom
R722  -  [RES_0402]  45.4 36.83 0 bottom
R723  -  [RES_0402]  39.37 41.91 0 bottom
R724  -  [RES_0402]  39.37 39.37 0 bottom
R725  -  [RES_0402]  39.37 36.83 0 bottom
R726  -  [RES_0402]  172.09 29.21 0 bottom
R727  -  [RES_0402]  39.37 34.29 0 bottom
R728  -  [RES_0402]  39.37 31.75 0 bottom
R729  -  [RES_0402]  39.37 29.21 0 bottom
R730  68  [RES_1210]  167.77 21.34 0 bottom
R731  68  [RES_1210]  155.7 21.34 0 bottom
R732  68  [RES_1210]  142.37 21.34 0 bottom
R733  -  [RES_0402]  46.67 26.99 0 bottom
R734  -  [RES_0402]  39.05 25.08 0 bottom
R735  -  [RES_0402]  193.01 16.51 180 bottom
R736  -  [RES_0402]  192.99 17.27 180 bottom
R737  -  [RES_0603]  193.72 10.79 180 bottom
R738  -  [RES_0603]  193.72 12.12 180 bottom
R739  -  [RES_0603]  193.88 14.63 180 bottom
R740  -  [RES_0402]  191.13 14.61 180 bottom
R741  -  [RES_0402]  190.63 13.33 180 bottom
R742  2.4  [RES_1210]  163.45 19.43 270 bottom
R743  2.4  [RES_1210]  151.38 19.43 270 bottom
R744  2.4  [RES_1210]  138.05 19.43 270 bottom
R745  -  [RES_0402]  133.03 19.81 90 bottom
R746  -  [RES_0402]  54.36 13.72 0 bottom
R747  -  [RES_0402]  54.23 18.16 0 bottom
R748  -  [RES_0402]  54.23 16.13 0 bottom
R749  -  [RES_0402]  43.05 15.49 180 bottom
R750  -  [RES_0402]  43.05 13.46 180 bottom
R751  -  [RES_0402]  16.26 14.35 180 bottom
R752  -  [RES_0402]  192.99 18.31 180 bottom
R753  -  [RES_0402]  193.52 19.58 180 bottom
R754  -  [RES_0402]  190.94 12.06 180 bottom
R755  -  [RES_0402]  187.01 11.43 0 bottom
R756  -  [RES_0402]  185.42 8.38 0 bottom
R757  -  [RES_0402]  183.51 13.02 270 bottom
R758  -  [RES_0402]  176.15 8.51 0 bottom
R759  68  [RES_1210]  167.77 7.37 0 bottom
R760  68  [RES_1210]  155.7 7.37 0 bottom
R761  68  [RES_1210]  143.64 7.37 0 bottom
R762  -  [RES_0603]  110.74 10.92 0 bottom
R763  -  [RES_0402]  110.24 9.53 0 bottom
R764  -  [RES_0402]  108.58 9.91 90 bottom
R765  -  [RES_0402]  106.93 9.91 270 bottom
R766  -  [RES_0402]  105.92 9.91 90 bottom
R767  -  [RES_0603]  104.65 10.54 90 bottom
R768  -  [RES_0603]  66.04 6.6 90 bottom
R769  -  [RES_0402]  59.82 7.11 270 bottom
R770  -  [RES_0402]  42.55 6.1 270 bottom
R771  -  [RES_0402]  43.81 6.1 270 bottom
R772  -  [RES_0402]  22.61 8 270 bottom
R773  -  [RES_0402]  21.46 8 90 bottom
R774  -  [RES_0402]  9.78 7.11 0 bottom
R775  -  [RES_0402]  9.78 6.1 0 bottom
R776  -  [RES_0402]  172.34 3.43 0 bottom
R777  2.4  [RES_1210]  163.45 5.46 270 bottom
R778  2.4  [RES_1210]  151.38 5.46 270 bottom
R779  2.4  [RES_1210]  139.32 5.46 270 bottom
R780  -  [RES_0805]  115.95 3.43 0 bottom
R781  -  [RES_0805]  104.52 3.43 0 bottom
R782  -  [RES_0603]  75.95 3.3 180 bottom
R783  -  [RES_0402]  19.81 3.81 90 bottom
R784  -  [RES_0402]  18.41 3.81 90 bottom
R785  -  [RES_0402]  15.88 3.3 270 bottom
R786  -  [RES_0402]  14.99 3.3 270 bottom
R787  -  [RES_0402]  13.34 3.3 90 bottom
R788  -  [RES_0402]  24.77 72.77 180 bottom
R789  -  [RES_0402]  73.91 87.88 0 bottom
R790  -  [RES_0402]  24.38 75.18 270 bottom
R791  -  [RES_0402]  74.42 85.09 0 bottom
R792  -  [RES_0402]  73.53 90.55 0 bottom
R793  -  [RES_0402]  19.94 72.64 0 bottom
R794  -  [RES_0402]  75.31 90.55 0 bottom
R795  -  [RES_0402]  76.33 85.09 0 bottom
R796  -  [RES_0402]  76.33 87.88 0 bottom
RN1  -  [RNET8-EXB38V_PAN]  42.86 82.55 270 top
RN500  -  [RNET8-EXB38V_PAN]  53.02 109.86 0 bottom
RN501  -  [RNET8-EXB38V_PAN]  43.81 100.33 180 bottom
RN502  -  [RNET8-EXB38V_PAN]  56.83 92.08 180 bottom
RN503  -  [RNET8-EXB38V_PAN]  43.81 93.98 180 bottom
RN504  -  [RNET8-EXB38V_PAN]  56.83 87.95 180 bottom
RN505  -  [RNET8-EXB38V_PAN]  50.16 88.9 0 bottom
RN506  -  [RNET8-EXB38V_PAN]  50.16 83.82 0 bottom
RN507  -  [RNET16-EXB-2HV_PAN]  74.87 70.61 180 bottom
RN508  -  [RNET16-EXB-2HV_PAN]  74.87 66.17 180 bottom
SW1  -  [SW_GT12]  63.88 12.57 0 top
TP1  -  [TP]  133.67 118.75 0 top
TP2  -  [TP]  134.3 114.3 0 top
TP3  -  [TP]  167.18 114.2 270 top
TP4  -  [TP]  29.97 107.19 0 top
TP5  -  [TP]  32.7 107.31 0 top
TP6  -  [TP]  46.04 110.49 0 top
TP7  -  [TP]  84.45 109.86 0 top
TP8  -  [TP]  105.09 106.68 0 top
TP9  -  [TP]  106.87 103.12 0 top
TP10  -  [TP]  108.65 105.41 0 top
TP11  -  [TP]  110.3 103.12 0 top
TP12  -  [TP]  111.57 105.16 0 top
TP13  -  [TP]  114.1 103.58 0 top
TP14  -  [TP]  118.2 106.27 0 top
TP15  -  [TP]  118.25 104.11 0 top
TP16  -  [TP]  134.24 106.3 270 top
TP17  -  [TP]  162.35 101.73 0 top
TP18  -  [TP]  29.97 99.06 0 top
TP19  -  [TP]  52.7 93.98 0 top
TP20  -  [TP]  129.62 93.27 0 top
TP21  -  [TP]  141.22 98.04 270 top
TP22  -  [TP]  145.03 96.9 270 top
TP23  -  [TP]  135.64 90.22 0 top
TP24  -  [TP]  33.66 83.31 0 top
TP25  -  [TP]  33.97 80.64 0 top
TP26  -  [TP]  36.83 83.31 0 top
TP27  -  [TP]  39.75 83.31 0 top
TP28  -  [TP]  41.66 85.6 0 top
TP29  -  [TP]  46.16 85.85 0 top
TP30  -  [TP]  127.95 79.38 0 top
TP31  -  [TP]  156.21 85.72 270 top
TP32  -  [TP]  129.86 74.3 0 top
TP33  -  [TP]  143.13 75.18 270 top
TP34  -  [TP]  16.19 63.82 0 top
TP35  -  [TP]  17.78 61.59 0 top
TP36  -  [TP]  19.37 63.82 0 top
TP37  -  [TP]  20.95 61.59 0 top
TP38  -  [TP]  22.54 63.82 0 top
TP39  -  [TP]  23.5 61.59 0 top
TP40  -  [TP]  155.77 65.91 270 top
TP41  -  [TP]  165.91 61.49 270 top
TP42  -  [TP]  127.57 56.9 0 top
TP43  -  [TP]  135.45 54.93 270 top
TP44  -  [TP]  164.34 54.36 270 top
TP45  -  [TP]  109.28 43.94 0 top
TP46  -  [TP]  133.35 44.58 180 top
TP47  -  [TP]  139.95 45.34 270 top
TP48  -  [TP]  143.76 44.2 270 top
TP49  -  [TP]  171.32 52.45 270 top
TP50  -  [TP]  175.58 48.9 270 top
TP51  -  [TP]  178.18 49.53 0 top
TP52  -  [TP]  116.52 41.27 0 top
TP53  -  [TP]  190.37 40.26 0 top
TP54  -  [TP]  100.71 33.66 0 top
TP55  -  [TP]  120.65 31.75 0 top
TP56  -  [TP]  120.33 34.61 0 top
TP57  -  [TP]  122.87 34.61 0 top
TP58  -  [TP]  39.57 12.04 0 top
TP59  -  [TP]  42.58 10.19 0 top
TP60  -  [TP]  49.46 11.38 0 top
TP61  -  [TP]  58.25 12.9 0 top
TP62  -  [TP]  84.45 10.92 0 top
TP63  -  [TP]  86.74 11.05 0 top
TP64  -  [TP]  88.77 11.05 0 top
TP65  -  [TP]  91.44 11.05 0 top
TP66  -  [TP]  96.52 10.16 0 top
TP67  -  [TP]  100.97 13.46 0 top
TP68  -  [TP]  104.14 13.97 0 top
TP69  -  [TP]  106.68 13.97 0 top
TP70  -  [TP]  114.3 10.79 0 top
TP71  -  [TP]  14.48 8.76 0 top
TP500  -  [TP]  191.01 88.52 180 bottom
U1  -  [VISHAY_IR_TSOP348]  15.24 120.65 180 top
U2  -  [QF48_PPAD]  161.16 113.54 180 top
U3  -  [LCC8-MXD2125_MEMSIC]  182.63 115.06 180 top
U4  -  [SOIC56-DGG_TI]  75.31 107.25 180 top
U5  -  [LCC8-MXD2125_MEMSIC]  182.63 107.44 180 top
U6  -  [SOIC16-PW_TI]  189.74 106.05 180 top
U7  -  [PQFP100-PZ_TI]  40.64 96.52 0 top
U8  -  [SOIC24-PW_TI]  60.96 90.17 270 top
U9  -  [SSOP_8]  130.75 83.69 180 top
U10  -  [SSOP_8]  135.19 83.69 180 top
U11  -  [BGA552-DDP4422_TI_MOD]  93.66 76.2 0 top
U12  -  [SOIC16-PW_TI]  190.12 73.53 180 top
U13  -  [TSOPII_44]  38.1 67.94 90 top
U14  -  [TSOP_56_48_DUAL_SKT]  55.24 68.58 90 top
U15  -  [QF48_PPAD]  159.89 60.83 180 top
U16  -  [TSSOP_8]  177.42 24.26 270 top
U17  -  [SOIC8-PW_TI]  183.13 28.83 180 top
U18  -  [SOT23-DBV_TI]  129.54 18.8 180 top
U19  -  [SOIC6-DBV_TI]  177.42 20.19 0 top
U20  -  [PQFP24-QFN_SI]  185.42 13.65 180 top
U21  -  [VISHAY_IR_TSOP348]  183.51 4.45 0 top
U500  -  [SOT23-DBV_TI]  15.24 124.46 180 bottom
U501  -  [TSSOP_14]  174.94 117.22 0 bottom
U502  -  [CRY4-P73_ECS]  40.32 112.14 270 bottom
U503  -  [SOIC6-DBV_TI]  12.57 113.67 270 bottom
U504  -  [SOT23-DBV_TI]  13.72 107.44 0 bottom
U505  -  [SOIC8-D_TI]  181.48 96.65 270 bottom
U506  -  [SOIC24-PW_TI]  24.33 83.82 270 bottom
U507  -  [SOIC6-DRL_TI]  22.75 75.56 0 bottom
U508  -  [SOIC14-PW_TI]  184.91 72.77 270 bottom
U509  -  [SOIC6-DRL_TI]  22.75 70.8 0 bottom
U510  -  [TSSOP_14]  141.16 62.99 90 bottom
U511  -  [SOT23-DBV_TI]  122.43 62.23 180 bottom
U512  -  [TSSOP_14]  141.29 57.4 90 bottom
U513  -  [SOT23-DBV_TI]  43.18 44.77 90 bottom
U514  -  [SOT23-DBV_TI]  43.18 48.58 270 bottom
U515  -  [SOIC8-PW_TI]  133.86 41.66 90 bottom
U516  -  [SOT23-DBV_TI]  42.86 26.04 90 bottom
U517  -  [SOIC24-PW_TI]  28.77 22.48 270 bottom
U518  -  [SOIC16-PW_TI]  48.9 15.88 270 bottom
U519  -  [SOIC24-PW_TI]  7.11 14.48 90 bottom
U520  -  [SOT23-DBV_TI]  182.12 7.49 270 bottom
U521  -  [SOIC8-PW_TI]  106.81 7.11 270 bottom
U522  -  [SOT23-DBV_TI]  74.17 6.35 0 bottom
U523  -  [SOT23-DBV_TI]  62.74 6.6 90 bottom
U524  -  [SOT23-DBV_TI]  17.14 8 180 bottom
U525  -  [SOIC5-DBV_TI]  15.49 12.19 0 bottom
U526  -  [SOT23-DBV_TI]  12.32 6.6 0 bottom
VR1  -  [POT-3314G]  95.76 12.95 90 top
VR2  -  [POT-3314G]  119.38 12.7 270 top
X500  -  [SMD_49]  91.82 100.84 0 bottom

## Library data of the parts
C1 C17 C22 C27 C32 C525 C529 C538 C543 C545 C566 C583 C674 C676 C680 C689-C691 C700-C702 = CAP_1210: Tolerance: TOL
C2-C5 C9-C14 C25 C26 C30 C31 C34-C36 C503 C504 C508 C509 C511 C514 C516-C518 C521-C524 C526 C530-C534 C536 C537 C542 C544 C546-C550 C556 C557 C559-C562 C567-C573 C579 C584-C607 C611-C636 C643-C663 C673 C679 C683-C688 C692 C693 C695 C697 C698 C705 C707 C709 = CAP_0402
C6-C8 C18-C21 C23 C24 C33 C37 C500-C502 C505-C507 C512 C513 C515 C519 C520 C535 C540 C552 C555 C558 C563-C565 C576-C578 C580-C582 C608 C610 C637 C639-C641 C665 C666 C668 C669 C671 C677 = CAP_0805
C15 C16 C574 C575 C609 C670 = CAP_1206
C28 C29 C510 C527 C528 C539 C541 C551 C642 C667 C675 C678 C681 C682 C694 C696 C699 C703 C704 C706 C708 = CAP_0603
C553 C554 R1 R2 R7-R10 R12 R13 R15 R16 R21 R22 R24 R26-R30 R34-R38 R40-R52 R54-R58 R63-R66 R503-R511 R514 R519-R524 R526-R536 R538 R540-R571 R573-R575 R577-R586 R588 R590-R600 R603-R619 R621-R631 R633 R635-R686 R688-R712 R714-R716 R719 R720 R722-R729 R733-R736 R740 R741 R745-R758 R763-R766 R769-R776 R783-R796 = RES_0402
C638 C664 C672 = CAP-FK-V-CASEE_PAN
D1-D4 D6-D8 = DIO-SMA
D5 = SMC_ST
D9-D12 = LED_S_TYPE
D500 D502 = DIO-SMB
D501 = DIO_SMA
D503-D508 = SOD-123
DN500-DN503 DN505-DN508 = SOT_323
DN504 = SOT23AVXC
FB1-FB7 FB9 FB10 = FLTR_0603
FB8 = IND_0805
FB500-FB504 = 0805AVX
J1 = HDR14-87227_AMP
J2 J3 = CN120_QTH_SAMTEC
J4 J8 J12-J16 J18 J19 J26 J34 J45 J46 J51 = HDR1X3-TMM1030X-X-S_SAM
J5 = CONN4-67068-1000_MOLEX
J6 J7 J17 J25 J36 J48 J50 = HDR2_2MM
J9 J47 J49 J53 = CONN6-53398-0690_MOLEX
J10 J21 = KYCON-CN9SMTA
J11 J22 = CONN5-53398-0590_MOLEX
J20 = CONN10-SQT_SAM
J23 = CONN22-B22B-PHD_JST
J24 = CONN20-TSM-110-0X-X-DV-A_SAMTEC
J27 = JACK3-DCPOWER_CUI_MOD
J28 = HDR10X2-5103308_TYCO
J29 J41 J54-J56 = CONN4-53398_MOLEX
J30 J31 J35 J42-J44 J57 J58 J60 J62 J64-J67 = CN3_53398_MOLEX
J32 = MICTOR_HPA
J33 = CONN12-SMT-TSM-112-SV_SAMTEC
J37 = CONN8-43045-0813_MOLEX
J38 J39 = CONN12-53398_MOLEX
J40 = CONN14-53048_MLX
J52 = CONN14-XF2M_OMRON
J59 = CONN12-FH12_HRS
J61 J63 = CONN4-52808_MOLEX
J500 = CN150CUSTOM_REV
L1-L8 = IND_SRR1005
L500 = IND2-SPR7030_BOU
L501-L506 = IND_SERH
MT1-MT6 = MH276-157GND
Q1 Q2 Q500 Q505 = SM_TO_252_DPAK
Q3 Q4 Q501-Q504 Q507 = SOT23AVXD
Q5 = SOT223
Q506 = SOT23-3_FC
R3 R4 R6 R11 R14 R17-R20 R25 R31-R33 R53 R525 R576 R587 R620 R632 R634 R713 R717 R718 R780 R781 = RES_0805
R5 R23 R500-R502 R589 R601 R602 = RES_1206
R39 R59-R62 R512 R513 R517 R518 R537 R539 R572 R687 R721 R737-R739 R762 R767 R768 R782 = RES_0603
R515 R516 = RES_2010
R730-R732 R742-R744 R759-R761 R777-R779 = RES_1210: Tolerance: TOL
RN1 RN500-RN506 = RNET8-EXB38V_PAN
RN507 RN508 = RNET16-EXB-2HV_PAN
SW1 = SW_GT12
TP1-TP71 TP500 = TP
U1 U21 = VISHAY_IR_TSOP348
U2 U15 = QF48_PPAD
U3 U5 = LCC8-MXD2125_MEMSIC
U4 = SOIC56-DGG_TI
U6 U12 U518 = SOIC16-PW_TI
U7 = PQFP100-PZ_TI
U8 U506 U517 U519 = SOIC24-PW_TI
U9 U10 = SSOP_8
U11 = BGA552-DDP4422_TI_MOD
U13 = TSOPII_44
U14 = TSOP_56_48_DUAL_SKT
U16 = TSSOP_8
U17 U515 U521 = SOIC8-PW_TI
U18 U500 U504 U511 U513 U514 U516 U520 U522-U524 U526 = SOT23-DBV_TI
U19 U503 = SOIC6-DBV_TI
U20 = PQFP24-QFN_SI
U501 U510 U512 = TSSOP_14
U502 = CRY4-P73_ECS
U505 = SOIC8-D_TI
U507 U509 = SOIC6-DRL_TI
U508 = SOIC14-PW_TI
U525 = SOIC5-DBV_TI
VR1 VR2 = POT-3314G
X500 = SMD_49

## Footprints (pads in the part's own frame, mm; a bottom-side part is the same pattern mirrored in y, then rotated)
0805AVX
  rect 1.27x1.524 smd: 1(-0.965,0) 2(0.965,0)
BGA552-DDP4422_TI_MOD
  round 0.559 smd: A1(-12.5,-12.5) A2(-12.5,-11.5) A3(-12.5,-10.5) A4(-12.5,-9.5) A5(-12.5,-8.5) A6(-12.5,-7.5) A7(-12.5,-6.5) A8(-12.5,-5.5) A9(-12.5,-4.5) A10(-12.5,-3.5) A11(-12.5,-2.5) A12(-12.5,-1.5) A13(-12.5,-0.5) A14(-12.5,0.5) A15(-12.5,1.5) A16(-12.5,2.5) A17(-12.5,3.5) A18(-12.5,4.5) A19(-12.5,5.5) A20(-12.5,6.5) A21(-12.5,7.5) A22(-12.5,8.5) A23(-12.5,9.5) A24(-12.5,10.5) A25(-12.5,11.5) A26(-12.5,12.5) AA1(7.5,-12.5) AA2(7.5,-11.5) AA3(7.5,-10.5) AA4(7.5,-9.5) AA5(7.5,-8.5) AA6(7.5,-7.5) AA7(7.5,-6.5) AA8(7.5,-5.5) AA9(7.5,-4.5) AA10(7.5,-3.5) AA11(7.5,-2.5) AA12(7.5,-1.5) AA13(7.5,-0.5) AA14(7.5,0.5) AA15(7.5,1.5) AA16(7.5,2.5) AA17(7.5,3.5) AA18(7.5,4.5) AA19(7.5,5.5) AA20(7.5,6.5) AA21(7.5,7.5) AA22(7.5,8.5) AA23(7.5,9.5) AA24(7.5,10.5) AA25(7.5,11.5) AA26(7.5,12.5) AB1(8.5,-12.5) AB2(8.5,-11.5) AB3(8.5,-10.5) AB4(8.5,-9.5) AB5(8.5,-8.5) AB6(8.5,-7.5) AB7(8.5,-6.5) AB8(8.5,-5.5) AB9(8.5,-4.5) AB10(8.5,-3.5) AB11(8.5,-2.5) AB12(8.5,-1.5) AB13(8.5,-0.5) AB14(8.5,0.5) AB15(8.5,1.5) AB16(8.5,2.5) AB17(8.5,3.5) AB18(8.5,4.5) AB19(8.5,5.5) AB20(8.5,6.5) AB21(8.5,7.5) AB22(8.5,8.5) AB23(8.5,9.5) AB24(8.5,10.5) AB25(8.5,11.5) AB26(8.5,12.5) AC1(9.5,-12.5) AC2(9.5,-11.5) AC3(9.5,-10.5) AC4(9.5,-9.5) AC5(9.5,-8.5) AC6(9.5,-7.5) AC7(9.5,-6.5) AC8(9.5,-5.5) AC9(9.5,-4.5) AC10(9.5,-3.5) AC11(9.5,-2.5) AC12(9.5,-1.5) AC13(9.5,-0.5) AC14(9.5,0.5) AC15(9.5,1.5) AC16(9.5,2.5) AC17(9.5,3.5) AC18(9.5,4.5) AC19(9.5,5.5) AC20(9.5,6.5) AC21(9.5,7.5) AC22(9.5,8.5) AC23(9.5,9.5) AC24(9.5,10.5) AC25(9.5,11.5) AC26(9.5,12.5) AD1(10.5,-12.5) AD2(10.5,-11.5) AD3(10.5,-10.5) AD4(10.5,-9.5) AD5(10.5,-8.5) AD6(10.5,-7.5) AD7(10.5,-6.5) AD8(10.5,-5.5) AD9(10.5,-4.5) AD10(10.5,-3.5) AD11(10.5,-2.5) AD12(10.5,-1.5) AD13(10.5,-0.5) AD14(10.5,0.5) AD15(10.5,1.5) AD16(10.5,2.5) AD17(10.5,3.5) AD18(10.5,4.5) AD19(10.5,5.5) AD20(10.5,6.5) AD21(10.5,7.5) AD22(10.5,8.5) AD23(10.5,9.5) AD24(10.5,10.5) AD25(10.5,11.5) AD26(10.5,12.5) AE1(11.5,-12.5) AE2(11.5,-11.5) AE3(11.5,-10.5) AE4(11.5,-9.5) AE5(11.5,-8.5) AE6(11.5,-7.5) AE7(11.5,-6.5) AE8(11.5,-5.5) AE9(11.5,-4.5) AE10(11.5,-3.5) AE11(11.5,-2.5) AE12(11.5,-1.5) AE13(11.5,-0.5) AE14(11.5,0.5) AE15(11.5,1.5) AE16(11.5,2.5) AE17(11.5,3.5) AE18(11.5,4.5) AE19(11.5,5.5) AE20(11.5,6.5) AE21(11.5,7.5) AE22(11.5,8.5) AE23(11.5,9.5) AE24(11.5,10.5) AE25(11.5,11.5) AE26(11.5,12.5) AF1(12.5,-12.5) AF2(12.5,-11.5) AF3(12.5,-10.5) AF4(12.5,-9.5) AF5(12.5,-8.5) AF6(12.5,-7.5) AF7(12.5,-6.5) AF8(12.5,-5.5) AF9(12.5,-4.5) AF10(12.5,-3.5) AF11(12.5,-2.5) AF12(12.5,-1.5) AF13(12.5,-0.5) AF14(12.5,0.5) AF15(12.5,1.5) AF16(12.5,2.5) AF17(12.5,3.5) AF18(12.5,4.5) AF19(12.5,5.5) AF20(12.5,6.5) AF21(12.5,7.5) AF22(12.5,8.5) AF23(12.5,9.5) AF24(12.5,10.5) AF25(12.5,11.5) AF26(12.5,12.5) B1(-11.5,-12.5) B2(-11.5,-11.5) B3(-11.5,-10.5) B4(-11.5,-9.5) B5(-11.5,-8.5) B6(-11.5,-7.5) B7(-11.5,-6.5) B8(-11.5,-5.5) B9(-11.5,-4.5) B10(-11.5,-3.5) B11(-11.5,-2.5) B12(-11.5,-1.5) B13(-11.5,-0.5) B14(-11.5,0.5) B15(-11.5,1.5) B16(-11.5,2.5) B17(-11.5,3.5) B18(-11.5,4.5) B19(-11.5,5.5) B20(-11.5,6.5) B21(-11.5,7.5) B22(-11.5,8.5) B23(-11.5,9.5) B24(-11.5,10.5) B25(-11.5,11.5) B26(-11.5,12.5) C1(-10.5,-12.5) C2(-10.5,-11.5) C3(-10.5,-10.5) C4(-10.5,-9.5) C5(-10.5,-8.5) C6(-10.5,-7.5) C7(-10.5,-6.5) C8(-10.5,-5.5) C9(-10.5,-4.5) C10(-10.5,-3.5) C11(-10.5,-2.5) C12(-10.5,-1.5) C13(-10.5,-0.5) C14(-10.5,0.5) C15(-10.5,1.5) C16(-10.5,2.5) C17(-10.5,3.5) C18(-10.5,4.5) C19(-10.5,5.5) C20(-10.5,6.5) C21(-10.5,7.5) C22(-10.5,8.5) C23(-10.5,9.5) C24(-10.5,10.5) C25(-10.5,11.5) C26(-10.5,12.5) D1(-9.5,-12.5) D2(-9.5,-11.5) D3(-9.5,-10.5) D4(-9.5,-9.5) D5(-9.5,-8.5) D6(-9.5,-7.5) D7(-9.5,-6.5) D8(-9.5,-5.5) D9(-9.5,-4.5) D10(-9.5,-3.5) D11(-9.5,-2.5) D12(-9.5,-1.5) D13(-9.5,-0.5) D14(-9.5,0.5) D15(-9.5,1.5) D16(-9.5,2.5) D17(-9.5,3.5) D18(-9.5,4.5) D19(-9.5,5.5) D20(-9.5,6.5) D21(-9.5,7.5) D22(-9.5,8.5) D23(-9.5,9.5) D24(-9.5,10.5) D25(-9.5,11.5) D26(-9.5,12.5) E1(-8.5,-12.5) E2(-8.5,-11.5) E3(-8.5,-10.5) E4(-8.5,-9.5) E5(-8.5,-8.5) E6(-8.5,-7.5) E7(-8.5,-6.5) E8(-8.5,-5.5) E9(-8.5,-4.5) E10(-8.5,-3.5) E11(-8.5,-2.5) E12(-8.5,-1.5) E13(-8.5,-0.5) E14(-8.5,0.5) E15(-8.5,1.5) E16(-8.5,2.5) E17(-8.5,3.5) E18(-8.5,4.5) E19(-8.5,5.5) E20(-8.5,6.5) E21(-8.5,7.5) E22(-8.5,8.5) E23(-8.5,9.5) E24(-8.5,10.5) E25(-8.5,11.5) E26(-8.5,12.5) F1(-7.5,-12.5) F2(-7.5,-11.5) F3(-7.5,-10.5) F4(-7.5,-9.5) F5(-7.5,-8.5) F6(-7.5,-7.5) F7(-7.5,-6.5) F8(-7.5,-5.5) F9(-7.5,-4.5) F10(-7.5,-3.5) F11(-7.5,-2.5) F12(-7.5,-1.5) F13(-7.5,-0.5) F14(-7.5,0.5) F15(-7.5,1.5) F16(-7.5,2.5) F17(-7.5,3.5) F18(-7.5,4.5) F19(-7.5,5.5) F20(-7.5,6.5) F21(-7.5,7.5) F22(-7.5,8.5) F23(-7.5,9.5) F24(-7.5,10.5) F25(-7.5,11.5) F26(-7.5,12.5) G1(-6.5,-12.5) G2(-6.5,-11.5) G3(-6.5,-10.5) G4(-6.5,-9.5) G5(-6.5,-8.5) G6(-6.5,-7.5) G21(-6.5,7.5) G22(-6.5,8.5) G23(-6.5,9.5) G24(-6.5,10.5) G25(-6.5,11.5) G26(-6.5,12.5) H1(-5.5,-12.5) H2(-5.5,-11.5) H3(-5.5,-10.5) H4(-5.5,-9.5) H5(-5.5,-8.5) H6(-5.5,-7.5) H21(-5.5,7.5) H22(-5.5,8.5) H23(-5.5,9.5) H24(-5.5,10.5) H25(-5.5,11.5) H26(-5.5,12.5) J1(-4.5,-12.5) J2(-4.5,-11.5) J3(-4.5,-10.5) J4(-4.5,-9.5) J5(-4.5,-8.5) J6(-4.5,-7.5) J21(-4.5,7.5) J22(-4.5,8.5) J23(-4.5,9.5) J24(-4.5,10.5) J25(-4.5,11.5) J26(-4.5,12.5) K1(-3.5,-12.5) K2(-3.5,-11.5) K3(-3.5,-10.5) K4(-3.5,-9.5) K5(-3.5,-8.5) K6(-3.5,-7.5) K21(-3.5,7.5) K22(-3.5,8.5) K23(-3.5,9.5) K24(-3.5,10.5) K25(-3.5,11.5) K26(-3.5,12.5) L1(-2.5,-12.5) L2(-2.5,-11.5) L3(-2.5,-10.5) L4(-2.5,-9.5) L5(-2.5,-8.5) L6(-2.5,-7.5) L11(-2.5,-2.5) L12(-2.5,-1.5) L13(-2.5,-0.5) L14(-2.5,0.5) L15(-2.5,1.5) L16(-2.5,2.5) L21(-2.5,7.5) L22(-2.5,8.5) L23(-2.5,9.5) L24(-2.5,10.5) L25(-2.5,11.5) L26(-2.5,12.5) M1(-1.5,-12.5) M2(-1.5,-11.5) M3(-1.5,-10.5) M4(-1.5,-9.5) M5(-1.5,-8.5) M6(-1.5,-7.5) M11(-1.5,-2.5) M12(-1.5,-1.5) M13(-1.5,-0.5) M14(-1.5,0.5) M15(-1.5,1.5) M16(-1.5,2.5) M21(-1.5,7.5) M22(-1.5,8.5) M23(-1.5,9.5) M24(-1.5,10.5) M25(-1.5,11.5) M26(-1.5,12.5) N1(-0.5,-12.5) N2(-0.5,-11.5) N3(-0.5,-10.5) N4(-0.5,-9.5) N5(-0.5,-8.5) N6(-0.5,-7.5) N11(-0.5,-2.5) N12(-0.5,-1.5) N13(-0.5,-0.5) N14(-0.5,0.5) N15(-0.5,1.5) N16(-0.5,2.5) N21(-0.5,7.5) N22(-0.5,8.5) N23(-0.5,9.5) N24(-0.5,10.5) N25(-0.5,11.5) N26(-0.5,12.5) P1(0.5,-12.5) P2(0.5,-11.5) P3(0.5,-10.5) P4(0.5,-9.5) P5(0.5,-8.5) P6(0.5,-7.5) P11(0.5,-2.5) P12(0.5,-1.5) P13(0.5,-0.5) P14(0.5,0.5) P15(0.5,1.5) P16(0.5,2.5) P21(0.5,7.5) P22(0.5,8.5) P23(0.5,9.5) P24(0.5,10.5) P25(0.5,11.5) P26(0.5,12.5) R1(1.5,-12.5) R2(1.5,-11.5) R3(1.5,-10.5) R4(1.5,-9.5) R5(1.5,-8.5) R6(1.5,-7.5) R11(1.5,-2.5) R12(1.5,-1.5) R13(1.5,-0.5) R14(1.5,0.5) R15(1.5,1.5) R16(1.5,2.5) R21(1.5,7.5) R22(1.5,8.5) R23(1.5,9.5) R24(1.5,10.5) R25(1.5,11.5) R26(1.5,12.5) T1(2.5,-12.5) T2(2.5,-11.5) T3(2.5,-10.5) T4(2.5,-9.5) T5(2.5,-8.5) T6(2.5,-7.5) T11(2.5,-2.5) T12(2.5,-1.5) T13(2.5,-0.5) T14(2.5,0.5) T15(2.5,1.5) T16(2.5,2.5) T21(2.5,7.5) T22(2.5,8.5) T23(2.5,9.5) T24(2.5,10.5) T25(2.5,11.5) T26(2.5,12.5) U1(3.5,-12.5) U2(3.5,-11.5) U3(3.5,-10.5) U4(3.5,-9.5) U5(3.5,-8.5) U6(3.5,-7.5) U21(3.5,7.5) U22(3.5,8.5) U23(3.5,9.5) U24(3.5,10.5) U25(3.5,11.5) U26(3.5,12.5) V1(4.5,-12.5) V2(4.5,-11.5) V3(4.5,-10.5) V4(4.5,-9.5) V5(4.5,-8.5) V6(4.5,-7.5) V21(4.5,7.5) V22(4.5,8.5) V23(4.5,9.5) V24(4.5,10.5) V25(4.5,11.5) V26(4.5,12.5) W1(5.5,-12.5) W2(5.5,-11.5) W3(5.5,-10.5) W4(5.5,-9.5) W5(5.5,-8.5) W6(5.5,-7.5) W21(5.5,7.5) W22(5.5,8.5) W23(5.5,9.5) W24(5.5,10.5) W25(5.5,11.5) W26(5.5,12.5) Y1(6.5,-12.5) Y2(6.5,-11.5) Y3(6.5,-10.5) Y4(6.5,-9.5) Y5(6.5,-8.5) Y6(6.5,-7.5) Y21(6.5,7.5) Y22(6.5,8.5) Y23(6.5,9.5) Y24(6.5,10.5) Y25(6.5,11.5) Y26(6.5,12.5)
